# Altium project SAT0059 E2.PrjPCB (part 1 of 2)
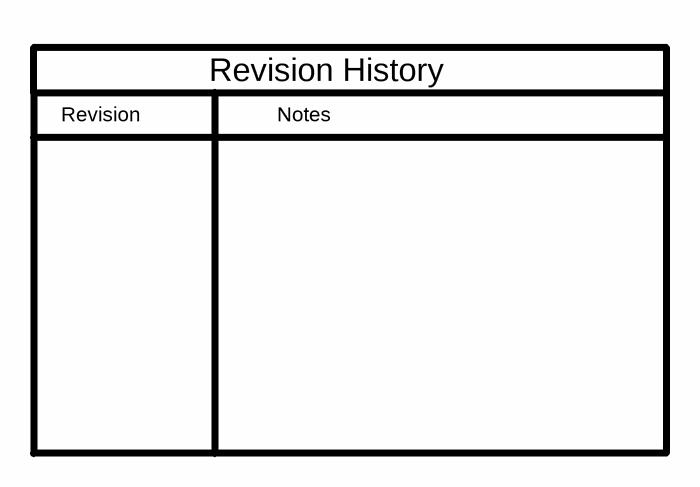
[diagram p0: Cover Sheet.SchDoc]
TechSupport: http://www.ti.com/support; SCH_Rev: E2; PRJ_Title: Touchscreen LCD (TIDA-00169); PRJ_Number: SAT0059; PRJ_Engineer: B. Shaffer; PRJ_Customer: Public Release; PCB_Rev: E2; PCB_Layout: Krypton Solutions; CopyrightYear: 2014
8 sheets, 276 parts. Net scope: global (net labels, ports and power ports of the same name join across sheets).
Board file: SAT0059 E2.PcbDoc
Sheets:
  Cover Sheet.SchDoc
  Power Supplies.SchDoc
  Deserializer.SchDoc
  LED Driver.SchDoc
  Haptic Drivers.SchDoc
  MCU.SchDoc
  Connectors.SchDoc
  Hardware.SchDoc

## Sheet Cover Sheet.SchDoc: Cover Sheet
size 431 x 279 mm; Date: Not shown in title block; ApprovedBy: Not shown in title block; CheckedBy: Not shown in title block; Author: Not shown in title block; CompanyName: Not shown in title block; DrawnBy: B. Shaffer; Engineer: Not shown in title block; Organization: Not shown in title block; Address1: Not shown in title block; Address2: Not shown in title block; Address3: Not shown in title block; Address4: Not shown in title block; DocumentNumber: 1; Revision: Use project parameter SCH_Rev; SheetNumber: 1; SheetTotal: 8; PageSetup: Record=PageOptions|CenterHorizontal=True|CenterVertical=True|PrintScale=1.00|XCorrection=1.00|YCorrection=1.00|PrintKind=0|BorderSize=5000000|LeftOffset=0|BottomOffset=0|Orientation=2|PaperLength=1000|PaperWidth=1000|Scale=100|PaperSource=15|PrintQuality=600|MediaType=1|DitherType=10|PaperKind=Letter|PrintScaleMode=1

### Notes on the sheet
- Revision
- Notes
- Revision History

## Sheet Power Supplies.SchDoc: Power Supply
size 431 x 279 mm; Date: Not shown in title block; ApprovedBy: Not shown in title block; CheckedBy: Not shown in title block; Author: Not shown in title block; CompanyName: Not shown in title block; DrawnBy: B. Shaffer; Engineer: Not shown in title block; Organization: Not shown in title block; Address1: Not shown in title block; Address2: Not shown in title block; Address3: Not shown in title block; Address4: Not shown in title block; DocumentNumber: 2; Revision: Use project parameter SCH_Rev; SheetNumber: 2; SheetTotal: 8; PageSetup: Record=PageOptions|CenterHorizontal=True|CenterVertical=True|PrintScale=0.96|XCorrection=1.00|YCorrection=1.00|PrintKind=0|BorderSize=5000000|LeftOffset=0|BottomOffset=0|Orientation=2|PaperLength=1000|PaperWidth=1000|Scale=100|PaperSource=15|PrintQuality=600|MediaType=1|DitherType=10|PaperKind=11x17|PrintScaleMode=1
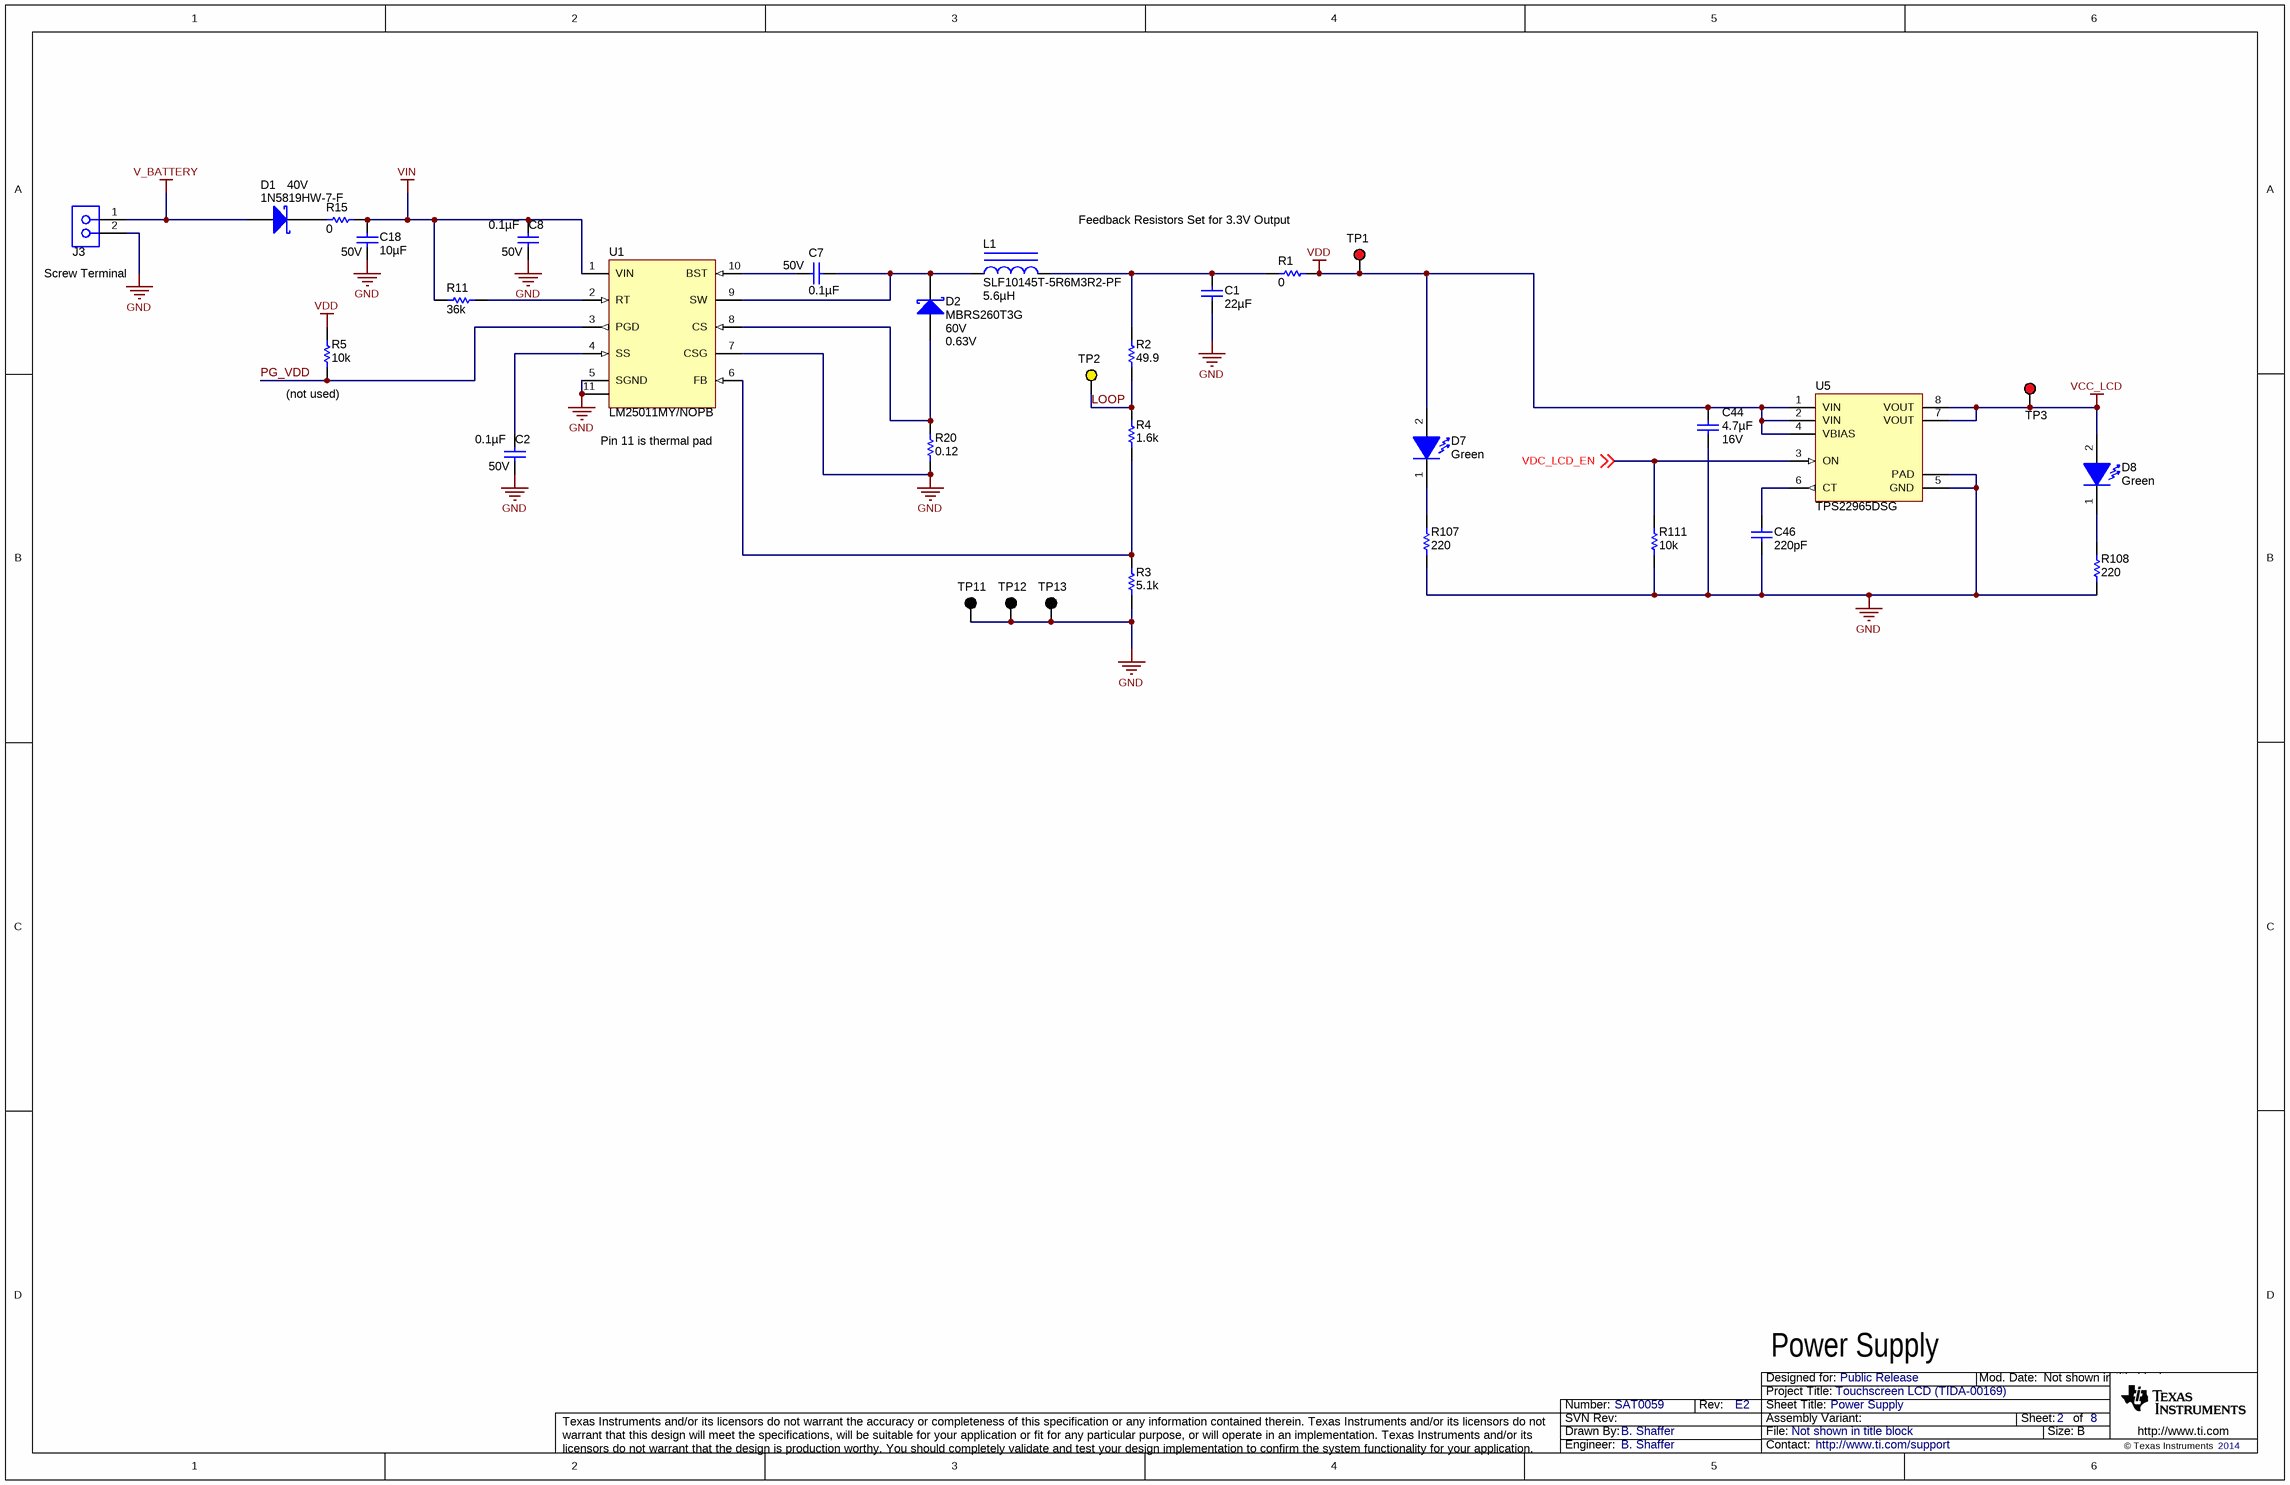
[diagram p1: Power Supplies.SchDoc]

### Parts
C1  ValueDisplayed: 22µF  [1210]  (hidden comment: C3225X7R1C226M)
C2  ValueDisplayed: 0.1µF  Value2: 50V  [0603]  (hidden comment: C1608X7R1H104K)
C7  ValueDisplayed: 0.1µF  Value2: 50V  [0603]  (hidden comment: C1608X7R1H104K)
C8  ValueDisplayed: 0.1µF  Value2: 50V  [0603]  (hidden comment: C1608X7R1H104K)
C18  ValueDisplayed: 10µF  Value2: 50V  [2220]  (hidden comment: C5750X7R1H106M)
C44  ValueDisplayed: 4.7µF  Value2: 16V  [0805_HV]  (hidden comment: EMK212BJ475KG-T)
C46  ValueDisplayed: 220pF  [0603]  (hidden comment: 06035A221JAT2A)
D1  1N5819HW-7-F  value 40V  [SOD-123]
D2  MBRS260T3G  value 60V  Value2: 0.63V  [SMB]
D7  value Green  [SML-P1_GREEN]  (hidden comment: SML-P12PTT86)
D8  value Green  [SML-P1_GREEN]  (hidden comment: SML-P12PTT86)
J3  1727010  [PhoenixConact_1727010]  (value not drawn)
L1  SLF10145T-5R6M3R2-PF  ValueDisplayed: 5.6µH  [SLF10145]
R1  value 0  [1210M]  (hidden comment: MCR25JZHJ000)
R2  value 49.9  [0402]  (hidden comment: CRCW040249R9FKED)
R3  value 5.1k  [0603]  (hidden comment: RC0603JR-075K1L)
R4  value 1.6k  [0603]  (hidden comment: RC0603JR-071K6L)
R5  value 10k  [0603]  (hidden comment: CRCW060310K0JNEA)
R11  value 36k  [0603]  (hidden comment: CRCW060336K0JNEA)
R15  value 0  [0603]  (hidden comment: CRCW06030000Z0EA)
R20  value 0.12  [1210M]  (hidden comment: ERJ14RSJR12U)
R107  value 220  [0402]  (hidden comment: CRCW0402220RJNED)
R108  value 220  [0402]  (hidden comment: CRCW0402220RJNED)
R111  value 10k  [0603]  (hidden comment: CRCW060310K0JNEA)
TP1  5000  [Keystone5000]  (value not drawn)
TP2  5004  [Keystone5004]  (value not drawn)
TP3  5000  [Keystone5000]  (value not drawn)
TP11  5001  [Keystone5001]  (value not drawn)
TP12  5001  [Keystone5001]  (value not drawn)
TP13  5001  [Keystone5001]  (value not drawn)
U1  LM25011MY/NOPB  [DGQ0010A_N]
U5  TPS22965DSG  [DSG0008A]

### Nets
GND: C1.2 C2.2 C8.2 C18.2 C44.2 C46.2 J3.2 R3.1 R20.1 R107.1 R108.1 R111.2 TP11.1 TP12.1 TP13.1 U1.5(SGND) U1.7(CSG) U1.11(PAD) U5.5(GND) U5.9(PAD)
V_BATTERY: D1.2(A) J3.1
VCC_LCD: D8.2(A) TP3.1 U5.7(VOUT) U5.8(VOUT)
VDD: C44.1 D7.2(A) R1.2 R5.1 TP1.1 U5.1(VIN) U5.2(VIN) U5.4(VBIAS)
VIN: C8.1 C18.1 R11.1 R15.1 U1.1(VIN)
LOOP: R2.1 R4.2 TP2.1
PG_VDD: R5.2 U1.3(PGD)
VDC_LCD_EN: R111.1 U5.3(ON) ; off-sheet VDC_LCD_EN
NetC1_1: C1.1 L1.2 R1.1 R2.2
NetC2_1: C2.1 U1.4(SS)
NetC7_1: C7.1 D2.1(K) L1.1 U1.9(SW)
NetC7_2: C7.2 U1.10(BST)
NetC46_1: C46.1 U5.6(CT)
NetD1_1: D1.1(K) R15.2
NetD2_2: D2.2(A) R20.2 U1.8(CS)
NetD7_1: D7.1(K) R107.2
NetD8_1: D8.1(K) R108.2
NetR3_2: R3.2 R4.1 U1.6(FB)
NetR11_2: R11.2 U1.2(RT)

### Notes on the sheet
- Feedback Resistors Set for 3.3V Output
- (near J3) Screw Terminal
- (near R5) (not used)
- (near U1) Pin 11 is thermal pad
- Power Supply

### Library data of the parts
C1 = C3225X7R1C226M: CAP, CERM, 22uF, 16V, +/-20%, X7R, 1210; Manufacturer: TDK; Polarized: N; CompType: Capacitor; U/M: EA; Cap_F: 0.000022; Tolerance_%: 20; ESR_Ohm: 0.002; Value1: 0.002 ohm; VDC_V: 16; IRMS_A: 8.11; TaMin_C: -55; TaMax_C: 125
C2 C7 C8 = C1608X7R1H104K: CAP, CERM, 0.1uF, 50V, +/-10%, X7R, 0603; Manufacturer: TDK; Polarized: N; CompType: Capacitor; U/M: EA; Cap_F: 0.0000001; Tolerance_%: 10; ESR_Ohm: 0.017; Value1: 0.017 ohm; VDC_V: 50; TaMin_C: -55; TaMax_C: 125
C18 = C5750X7R1H106M: CAP, CERM, 10uF, 50V, +/-20%, X7R, 2220; Manufacturer: TDK; Polarized: N; CompType: Capacitor; U/M: EA; Cap_F: 0.00001; Tolerance_%: 20; ESR_Ohm: 0.003; Value1: 0.003 ohm; VDC_V: 50; IRMS_A: 5.5; TaMin_C: -55; TaMax_C: 125
C44 = EMK212BJ475KG-T: CAP, CERM, 4.7uF, 16V, +/-10%, X5R, 0805; Manufacturer: Taiyo Yuden; Polarized: N; CompType: Capacitor; U/M: EA; Cap_F: 0.0000047; Tolerance_%: 10; Value1: Unknown; VDC_V: 16; TaMin_C: -55; TaMax_C: 85; Cap_Case: 0805
C46 = 06035A221JAT2A: CAP, CERM, 220pF, 50V, +/-5%, C0G/NP0, 0603; Manufacturer: AVX; Polarized: N; CompType: Capacitor; U/M: EA; Cap_F: 0.00000000022; Tolerance_%: 5; ESR_Ohm: 0.083; Value1: 0.083 ohm; VDC_V: 50; TaMin_C: -55; TaMax_C: 125
D1 = 1N5819HW-7-F: Diode, Schottky, 40V, 1A, SOD-123; Manufacturer: Diodes Inc.; U/M: EA; Vf_V: 0.45; Value2: 0.45V; Io_A: 1; Vr_V: 40; TJmax_C: 125
D2 = MBRS260T3G: Diode, Schottky, 60V, 2A, SMB; Manufacturer: ON Semiconductor; U/M: EA; Vf_V: 0.63; Io_A: 2; Vr_V: 60; TJmax_C: 125; RJC_CperW: 24
D7 D8 = SML-P12PTT86: LED, Green, SMD; Manufacturer: Rohm; Type: AlInGaP; Vf_V: 2.2; Value2: 2.2V; Io_A: 0.02; Value1: W; U/M: EA
J3 = 1727010: Conn Term Block, 2POS, 3.81mm PCB; Manufacturer: Phoenix Contact; Alternate Manufacturer: Any; Alternate PartNumber: Equivalent; Value: 2x1; CompType: Terminal Block; U/M: EA
L1 = SLF10145T-5R6M3R2-PF: Inductor, Shielded, Ferrite, 5.6uH, 3.8A, 0.0264 ohm, SMD; Manufacturer: TDK; Ind_H: 5.6E-6; Imax_A: 3.8; Irms: 3.2A @ 30C rise; Isat: 3.8A @ 10% inductance drop; DCR_ohm: 0.0264; U/M: EA
R1 = MCR25JZHJ000: RES, 0 ohm, 5%, 0.25W, 1210; Manufacturer: Rohm; CompType: Resistor; Value_Code: 0000; Tolerance_%: 5; Power_W: 0.25; VDC_V: 200; TempCo: 20 ppm/C; EIA_Code: E24; U/M: EA
R2 = CRCW040249R9FKED: RES, 49.9 ohm, 1%, 0.063W, 0402; Manufacturer: Vishay-Dale; CompType: Resistor; Value_Code: 49R9; Tolerance_%: 1; Power_W: 0.063; VDC_V: 50; TempCo: 100 ppm/C; EIA_Code: E96; U/M: EA
R3 = RC0603JR-075K1L: RES, 5.1k ohm, 5%, 0.1W, 0603; Manufacturer: Yageo America; CompType: Resistor; Res_ohm: 5100; Value_Code: 5k10; Tolerance_%: 5; Power_W: 0.1; VDC_V: 50; TempCo: 100 ppm/C; EIA_Code: E24; U/M: EA
R4 = RC0603JR-071K6L: RES, 1.6k ohm, 5%, 0.1W, 0603; Manufacturer: Yageo America; CompType: Resistor; Res_ohm: 1600; Value_Code: 1k60; Tolerance_%: 5; Power_W: 0.1; VDC_V: 50; TempCo: 100 ppm/C; EIA_Code: E24; U/M: EA
R5 R111 = CRCW060310K0JNEA: RES, 10k ohm, 5%, 0.1W, 0603; Manufacturer: Vishay-Dale; CompType: Resistor; Res_ohm: 10000; Value_Code: 10k0; Tolerance_%: 5; Power_W: 0.1; VDC_V: 75; TempCo: 200 ppm/C; EIA_Code: E24; U/M: EA
R11 = CRCW060336K0JNEA: RES, 36k ohm, 5%, 0.1W, 0603; Manufacturer: Vishay-Dale; CompType: Resistor; Res_ohm: 36000; Value_Code: 36k0; Tolerance_%: 5; Power_W: 0.1; VDC_V: 75; TempCo: 200 ppm/C; EIA_Code: E24; U/M: EA
R15 = CRCW06030000Z0EA: RES, 0 ohm, 5%, 0.1W, 0603; Manufacturer: Vishay-Dale; CompType: Resistor; Value_Code: 0000; Tolerance_%: 5; Power_W: 0.1; VDC_V: 75; TempCo: 200 ppm/C; EIA_Code: E24; U/M: EA
R20 = ERJ14RSJR12U: RES, 0.12 ohm, 5%, 0.25W, 1210; Manufacturer: Panasonic; CompType: Resistor; Value_Code: R120; Tolerance_%: 5; Power_W: 0.25; TempCo: 200 ppm/C; EIA_Code: E24; U/M: EA
R107 R108 = CRCW0402220RJNED: RES, 220 ohm, 5%, 0.063W, 0402; Manufacturer: Vishay-Dale; Alternate Manufacturer: Any; Alternate PartNumber: Equivalent; CompType: Resistor; Value_Code: 220R; Tolerance_%: 5; Power_W: 0.063; VDC_V: 50; TempCo: 200 ppm/C; EIA_Code: E24; U/M: EA
TP1 TP3 = 5000: Test Point, Miniature, Red, TH; Manufacturer: Keystone; CompType: Test Point Loop; U/M: EA
TP2 = 5004: Test Point, Miniature, Yellow, TH; Manufacturer: Keystone; CompType: Test Point Loop; U/M: EA
TP11-TP13 = 5001: Test Point, Miniature, Black, TH; Manufacturer: Keystone; CompType: Test Point Loop; U/M: EA
U1 = LM25011MY/NOPB: 42V 2A Constant On-Time Switching Regulator With Adjustable Current Limit, DGQ0010A; Alternate Manufacturer: None; Manufacturer: Texas Instruments; SymbolCreator: a0411947; CompType: IC; U/M: EA
U5 = TPS22965DSG: Single Channel, Ultra-Low Resistance Load Switch, DSG0008A; Alternate Manufacturer: None; Manufacturer: Texas Instruments; SymbolCreator: a0411947; CompType: IC; U/M: EA

## Sheet Deserializer.SchDoc: Deserializer
size 431 x 279 mm; Date: Not shown in title block; ApprovedBy: Not shown in title block; CheckedBy: Not shown in title block; Author: Not shown in title block; CompanyName: Not shown in title block; DrawnBy: B. Shaffer; Engineer: Not shown in title block; Organization: Not shown in title block; Address1: Not shown in title block; Address2: Not shown in title block; Address3: Not shown in title block; Address4: Not shown in title block; DocumentNumber: 3; Revision: Use project parameter SCH_Rev; SheetNumber: 3; SheetTotal: 8; PageSetup: Record=PageOptions|CenterHorizontal=True|CenterVertical=True|PrintScale=0.96|XCorrection=1.00|YCorrection=1.00|PrintKind=0|BorderSize=5000000|LeftOffset=0|BottomOffset=0|Orientation=2|PaperLength=1000|PaperWidth=1000|Scale=100|PaperSource=15|PrintQuality=600|MediaType=1|DitherType=10|PaperKind=11x17|PrintScaleMode=1
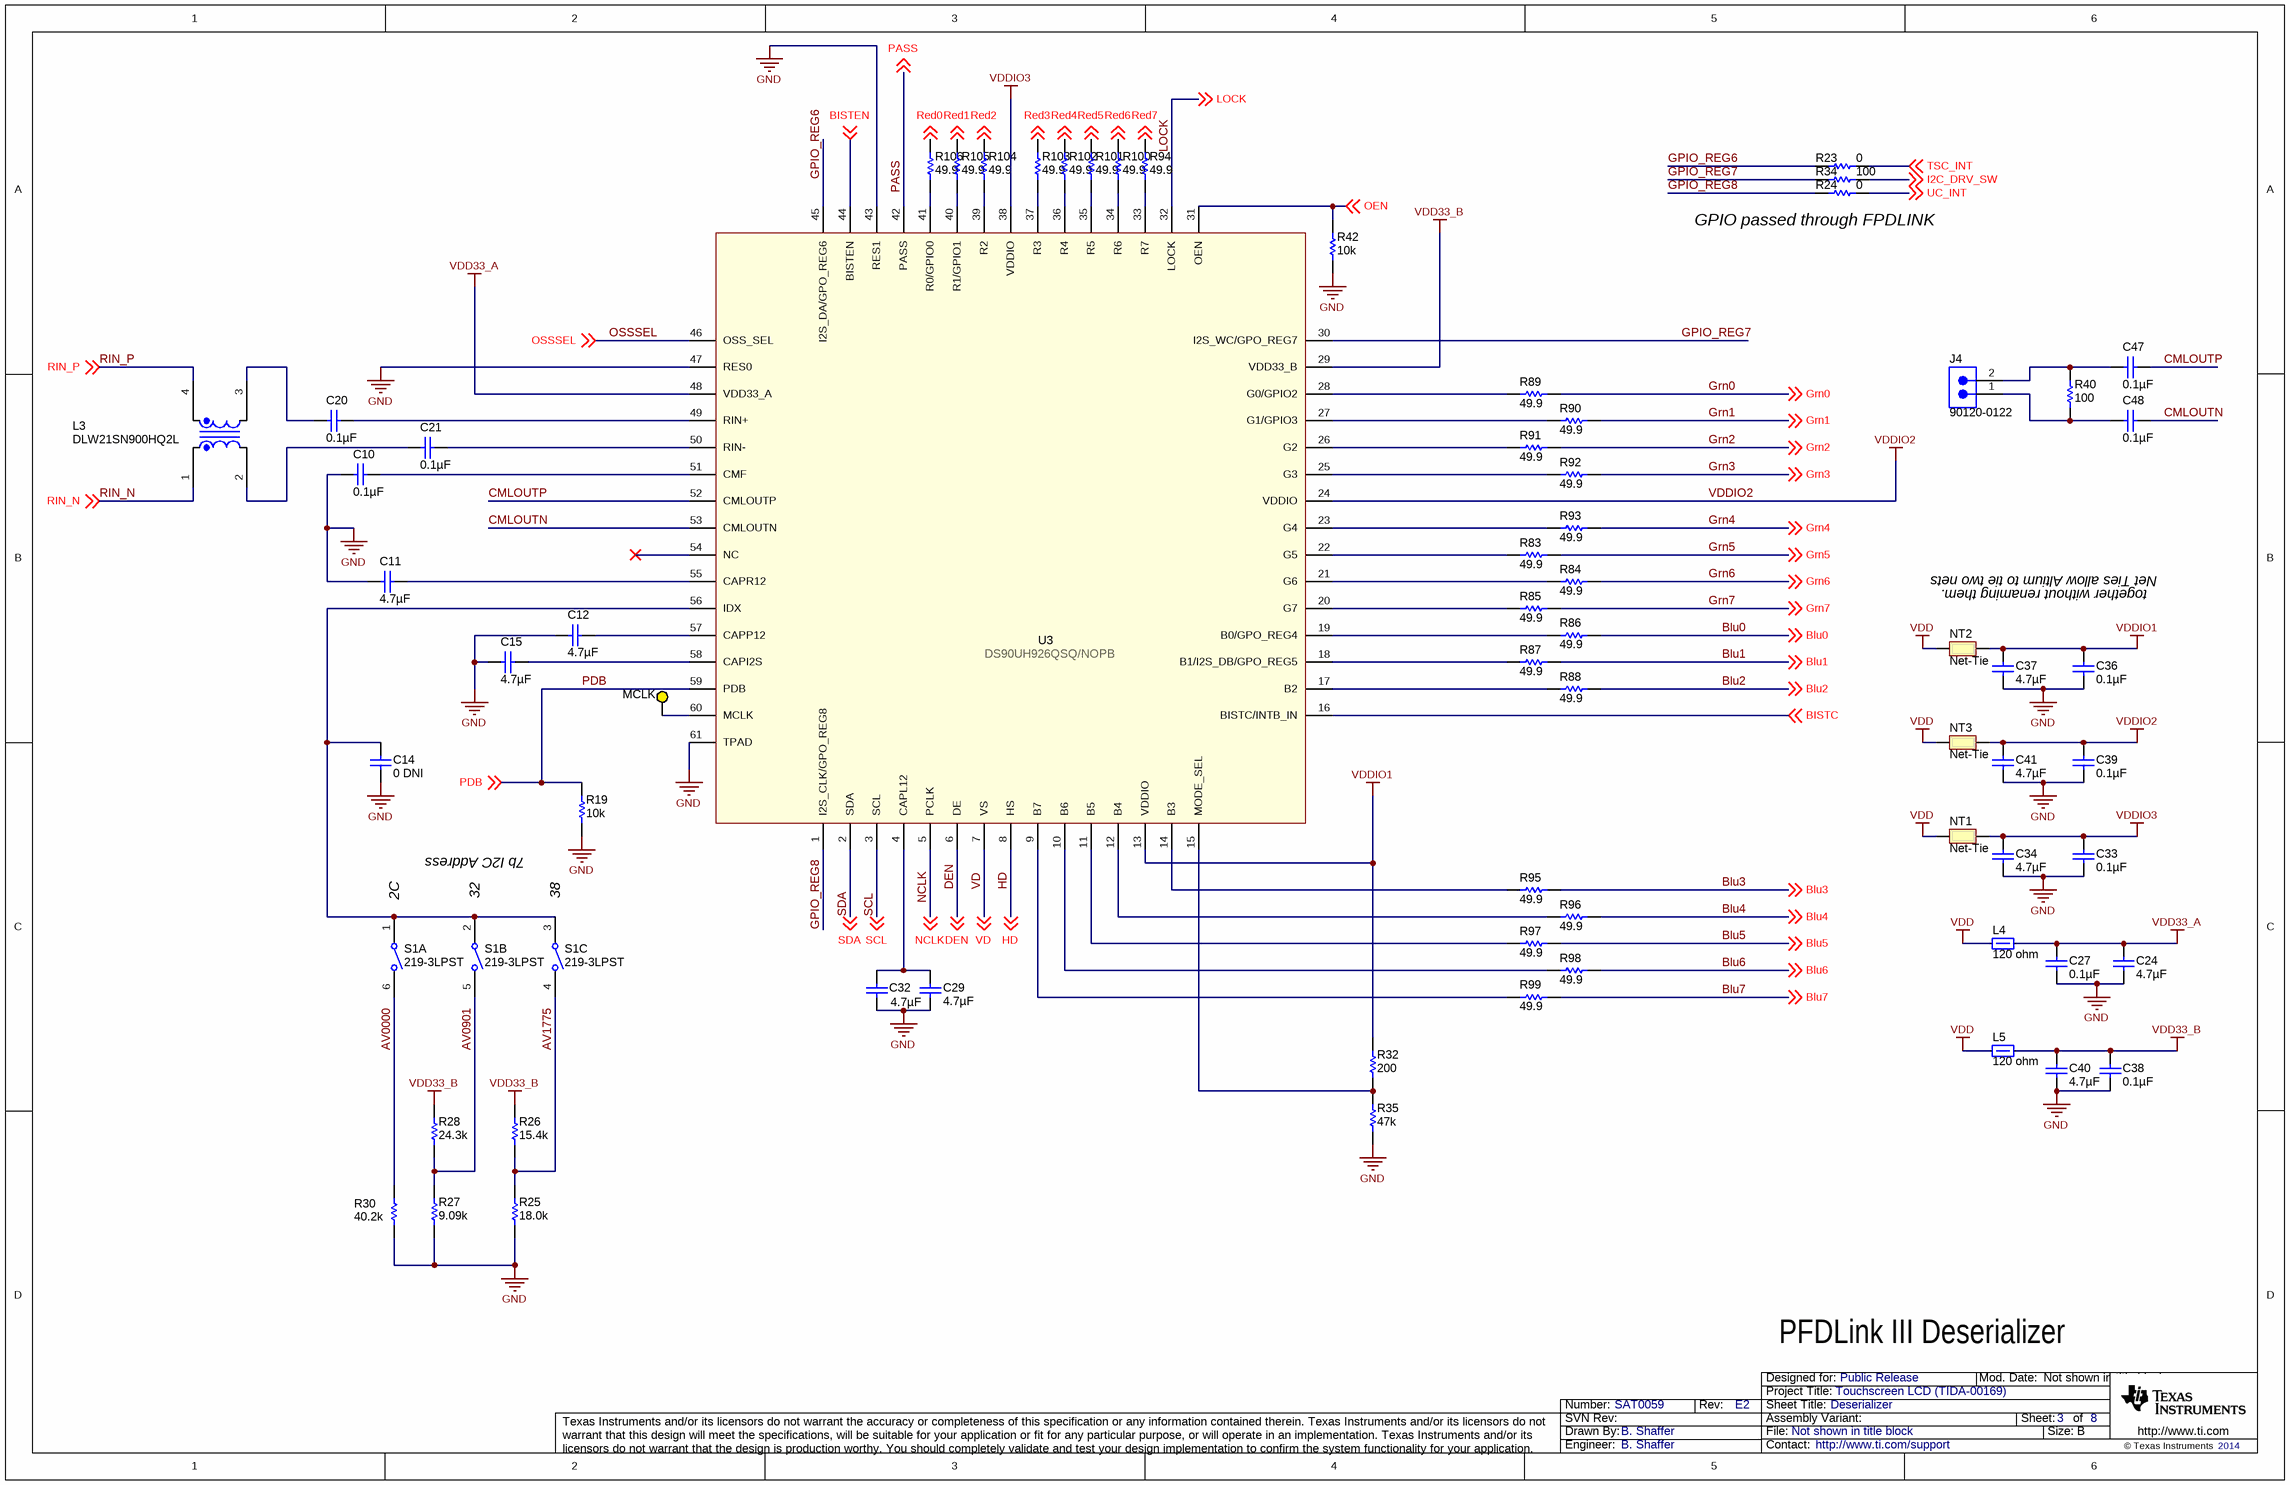
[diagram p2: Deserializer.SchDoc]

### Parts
C10  ValueDisplayed: 0.1µF  [0603]  (hidden comment: GCM188R71H104KA57B)
C11  ValueDisplayed: 4.7µF  [0805_HV]  (hidden comment: EMK212BJ475KG-T)
C12  ValueDisplayed: 4.7µF  [0805_HV]  (hidden comment: GRM21BR71A475KA73L)
C14  ValueDisplayed: 0 DNI  [0805]  (hidden comment: GCM188R71H104KA57B)
C15  ValueDisplayed: 4.7µF  [0805_HV]  (hidden comment: GRM21BR71A475KA73L)
C20  ValueDisplayed: 0.1µF  [0603]  (hidden comment: GCM188R71H104KA57B)
C21  ValueDisplayed: 0.1µF  [0603]  (hidden comment: GCM188R71H104KA57B)
C24  ValueDisplayed: 4.7µF  [0805_HV]  (hidden comment: GRM21BR71A475KA73L)
C27  ValueDisplayed: 0.1µF  [0603]  (hidden comment: 0603YC104JAT2A)
C29  ValueDisplayed: 4.7µF  [0805_HV]  (hidden comment: GRM21BR71A475KA73L)
C32  ValueDisplayed: 4.7µF  [0805_HV]  (hidden comment: GRM21BR71A475KA73L)
C33  ValueDisplayed: 0.1µF  [0603]  (hidden comment: 0603YC104JAT2A)
C34  ValueDisplayed: 4.7µF  [0805_HV]  (hidden comment: GRM21BR71A475KA73L)
C36  ValueDisplayed: 0.1µF  [0603]  (hidden comment: 0603YC104JAT2A)
C37  ValueDisplayed: 4.7µF  [0805_HV]  (hidden comment: GRM21BR71A475KA73L)
C38  ValueDisplayed: 0.1µF  [0603]  (hidden comment: 0603YC104JAT2A)
C39  ValueDisplayed: 0.1µF  [0603]  (hidden comment: 0603YC104JAT2A)
C40  ValueDisplayed: 4.7µF  [0805_HV]  (hidden comment: GRM21BR71A475KA73L)
C41  ValueDisplayed: 4.7µF  [0805_HV]  (hidden comment: GRM21BR71A475KA73L)
C47  ValueDisplayed: 0.1µF  [0603]  (hidden comment: GCM188R71H104KA57B)
C48  ValueDisplayed: 0.1µF  [0603]  (hidden comment: GCM188R71H104KA57B)
J4  90120-0122  [CONN_90120-0122]
L3  DLW21SN900HQ2L  [IND_DLW21S]
L4  value 120 ohm  [0603]  (hidden comment: BLM18SG121TN1D)
L5  value 120 ohm  [0603]  (hidden comment: BLM18SG121TN1D)
MCLK  5004  [Keystone5004]  (value not drawn)
NT1  Net-Tie  [Net-Tie_10mil]  (net tie, no BOM)
NT2  Net-Tie  [Net-Tie_10mil]  (net tie, no BOM)
NT3  Net-Tie  [Net-Tie_10mil]  (net tie, no BOM)
R19  value 10k  [0402]  (hidden comment: CRCW040210K0JNED)
R23  value 0  [0603]  (hidden comment: CRCW06030000Z0EA)
R24  value 0  [0603]  (hidden comment: CRCW06030000Z0EA)
R25  value 18.0k  [0603]  (hidden comment: RC0603FR-0718KL)
R26  value 15.4k  [0603]  (hidden comment: CRCW060315K4FKEA)
R27  value 9.09k  [0603]  (hidden comment: CRCW06039K09FKEA)
R28  value 24.3k  [0603]  (hidden comment: CRCW060324K3FKEA)
R30  value 40.2k  [0805_HV]  (hidden comment: CRCW080540K2FKEA)
R32  value 200  [0603]  (hidden comment: CRCW0603200RFKEA)
R34  value 100  [0603]  (hidden comment: CRCW0603100RFKEA)
R35  value 47k  [0603]  (hidden comment: CRCW060347K0JNEA)
R40  value 100  [0603]  (hidden comment: CRCW0603100RFKEA)
R42  value 10k  [0402]  (hidden comment: CRCW040210K0JNED)
R83  value 49.9  [0402]  (hidden comment: CRCW040249R9FKED)
R84  value 49.9  [0402]  (hidden comment: CRCW040249R9FKED)
R85  value 49.9  [0402]  (hidden comment: CRCW040249R9FKED)
R86  value 49.9  [0402]  (hidden comment: CRCW040249R9FKED)
R87  value 49.9  [0402]  (hidden comment: CRCW040249R9FKED)
R88  value 49.9  [0402]  (hidden comment: CRCW040249R9FKED)
R89  value 49.9  [0402]  (hidden comment: CRCW040249R9FKED)
R90  value 49.9  [0402]  (hidden comment: CRCW040249R9FKED)
R91  value 49.9  [0402]  (hidden comment: CRCW040249R9FKED)
R92  value 49.9  [0402]  (hidden comment: CRCW040249R9FKED)
R93  value 49.9  [0402]  (hidden comment: CRCW040249R9FKED)
R94  value 49.9  [0402]  (hidden comment: CRCW040249R9FKED)
R95  value 49.9  [0402]  (hidden comment: CRCW040249R9FKED)
R96  value 49.9  [0402]  (hidden comment: CRCW040249R9FKED)
R97  value 49.9  [0402]  (hidden comment: CRCW040249R9FKED)
R98  value 49.9  [0402]  (hidden comment: CRCW040249R9FKED)
R99  value 49.9  [0402]  (hidden comment: CRCW040249R9FKED)
R100  value 49.9  [0402]  (hidden comment: CRCW040249R9FKED)
R101  value 49.9  [0402]  (hidden comment: CRCW040249R9FKED)
R102  value 49.9  [0402]  (hidden comment: CRCW040249R9FKED)
R103  value 49.9  [0402]  (hidden comment: CRCW040249R9FKED)
R104  value 49.9  [0402]  (hidden comment: CRCW040249R9FKED)
R105  value 49.9  [0402]  (hidden comment: CRCW040249R9FKED)
R106  value 49.9  [0402]  (hidden comment: CRCW040249R9FKED)
S1  219-3LPST  [SW_219-3LPST]  (parts A,B,C of 3)
U3  DS90UH926QSQ/NOPB  [DS90UH926QSQ/NOPB]

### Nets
GND: C10.2 C11.2 C12.2 C14.2 C15.2 C24.2 C27.2 C29.2 C32.2 C33.2 C34.2 C36.2 C37.2 C38.2 C39.2 C40.2 C41.2 R19.1 R25.1 R27.1 R30.1 R35.1 R42.1 U3.43(RES1) U3.47(RES0) U3.61(TPAD)
VDD: L4.2 L5.2 NT1.1 NT2.1 NT3.1
VDD33_A: C24.1 C27.1 L4.1 U3.48(VDD33_A)
VDD33_B: C38.1 C40.1 L5.1 R26.2 R28.2 U3.29(VDD33_B)
VDDIO1: C36.1 C37.1 NT2.2 R32.2 U3.13(VDDIO)
VDDIO2: C39.1 C41.1 NT3.2 U3.24(VDDIO)
VDDIO3: C33.1 C34.1 NT1.2 U3.38(VDDIO)
AV0000: R30.2 S1.6(B1)
AV0901: R27.2 R28.1 S1.5(B2)
AV1775: R25.2 R26.1 S1.4(B3)
BISTC: U3.16(BISTC/INTB_IN) ; off-sheet BISTC
BISTEN: U3.44(BISTEN) ; off-sheet BISTEN
Blu0: R86.2 ; off-sheet Blu0
Blu1: R87.2 ; off-sheet Blu1
Blu2: R88.2 ; off-sheet Blu2
Blu3: R95.2 ; off-sheet Blu3
Blu4: R96.2 ; off-sheet Blu4
Blu5: R97.2 ; off-sheet Blu5
Blu6: R98.2 ; off-sheet Blu6
Blu7: R99.2 ; off-sheet Blu7
CMLOUTN: C48.1 U3.53(CMLOUTN)
CMLOUTP: C47.1 U3.52(CMLOUTP)
DEN: U3.6(DE) ; off-sheet DEN
GPIO_REG6: R23.2 U3.45(I2S_DA/GPO_REG6)
GPIO_REG7: R34.2 U3.30(I2S_WC/GPO_REG7)
GPIO_REG8: R24.2 U3.1(I2S_CLK/GPO_REG8)
Grn0: R89.2 ; off-sheet Grn0
Grn1: R90.2 ; off-sheet Grn1
Grn2: R91.2 ; off-sheet Grn2
Grn3: R92.2 ; off-sheet Grn3
Grn4: R93.2 ; off-sheet Grn4
Grn5: R83.2 ; off-sheet Grn5
Grn6: R84.2 ; off-sheet Grn6
Grn7: R85.2 ; off-sheet Grn7
HD: U3.8(HS) ; off-sheet HD
I2C_DRV_SW: R34.1 ; off-sheet I2C_DRV_SW
LOCK: U3.32(LOCK) ; off-sheet LOCK
NCLK: U3.5(PCLK) ; off-sheet NCLK
OEN: R42.2 U3.31(OEN) ; off-sheet OEN
OSSSEL: U3.46(OSS_SEL) ; off-sheet OSSSEL
PASS: U3.42(PASS) ; off-sheet PASS
PDB: R19.2 U3.59(PDB) ; off-sheet PDB
Red0: R106.2 ; off-sheet Red0
Red1: R105.2 ; off-sheet Red1
Red2: R104.2 ; off-sheet Red2
Red3: R103.2 ; off-sheet Red3
Red4: R102.2 ; off-sheet Red4
Red5: R101.2 ; off-sheet Red5
Red6: R100.2 ; off-sheet Red6
Red7: R94.2 ; off-sheet Red7
RIN_N: L3.1 ; off-sheet RIN_N
RIN_P: L3.4 ; off-sheet RIN_P
SCL: U3.3(SCL) ; off-sheet SCL
SDA: U3.2(SDA) ; off-sheet SDA
TSC_INT: R23.1 ; off-sheet TSC_INT
UC_INT: R24.1 ; off-sheet UC_INT
VD: U3.7(VS) ; off-sheet VD
NetC10_1: C10.1 U3.51(CMF)
NetC11_1: C11.1 U3.55(CAPR12)
NetC12_1: C12.1 U3.57(CAPP12)
NetC14_1: C14.1 S1.1(A1) S1.2(A2) S1.3(A3) U3.56(IDX)
NetC15_1: C15.1 U3.58(CAPI2S)
NetC20_1: C20.1 U3.49(RIN+)
NetC20_2: C20.2 L3.3
NetC21_1: C21.1 U3.50(RIN-)
NetC21_2: C21.2 L3.2
NetC29_1: C29.1 C32.1 U3.4(CAPL12)
NetC47_2: C47.2 J4.2 R40.2
NetC48_2: C48.2 J4.1 R40.1
NetMCLK_1: MCLK.1 U3.60(MCLK)
NetR32_1: R32.1 R35.2 U3.15(MODE_SEL)
NetR83_1: R83.1 U3.22(G5)
NetR84_1: R84.1 U3.21(G6)
NetR85_1: R85.1 U3.20(G7)
NetR86_1: R86.1 U3.19(B0/GPO_REG4)
NetR87_1: R87.1 U3.18(B1/I2S_DB/GPO_REG5)
NetR88_1: R88.1 U3.17(B2)
NetR89_1: R89.1 U3.28(G0/GPIO2)
NetR90_1: R90.1 U3.27(G1/GPIO3)
NetR91_1: R91.1 U3.26(G2)
NetR92_1: R92.1 U3.25(G3)
NetR93_1: R93.1 U3.23(G4)
NetR94_1: R94.1 U3.33(R7)
NetR95_1: R95.1 U3.14(B3)
NetR96_1: R96.1 U3.12(B4)
NetR97_1: R97.1 U3.11(B5)
NetR98_1: R98.1 U3.10(B6)
NetR99_1: R99.1 U3.9(B7)
NetR100_1: R100.1 U3.34(R6)
NetR101_1: R101.1 U3.35(R5)
NetR102_1: R102.1 U3.36(R4)
NetR103_1: R103.1 U3.37(R3)
NetR104_1: R104.1 U3.39(R2)
NetR105_1: R105.1 U3.40(R1/GPIO1)
NetR106_1: R106.1 U3.41(R0/GPIO0)

Not connected (* = marked no-connect by the designer): U3 54(NC)*

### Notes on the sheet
- (near R24) GPIO passed through FPDLINK
- Net Ties allow Altium to tie two nets
- together without renaming them.
- (near S1) 2C
- (near S1) 32
- 7b I2C Address
- 38
- PFDLink III Deserializer

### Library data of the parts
C10 C20 C21 C47 C48 = GCM188R71H104KA57B: CAP, CERM, 0.1uF, 50V, +/-10%, X7R, 0603; Manufacturer: MuRata; Polarized: N; CompType: Capacitor; U/M: EA; Cap_F: 0.0000001; Tolerance_%: 10; ESR_Ohm: 0.02; Value1: 0.02 ohm; VDC_V: 50; IRMS_A: 1.84; TaMin_C: -55; TaMax_C: 125
C11 = EMK212BJ475KG-T: as C44 on sheet Power Supplies
C12 C15 C24 C29 C32 C34 C37 C40 C41 = GRM21BR71A475KA73L: CAP, CERM, 4.7uF, 10V, +/-10%, X7R, 0805; Manufacturer: MuRata; Polarized: N; CompType: Capacitor; U/M: EA; Cap_F: 0.0000047; Tolerance_%: 10; Value1: Unknown; TaMin_C: -55; TaMax_C: 125; Cap_Case: 0805
C14 = GCM188R71H104KA57B: CAP, CERM, 0.1uF, 50V, +/-10%, X7R, 0603; Manufacturer: MuRata; Polarized: N; CompType: Capacitor; U/M: EA; Cap_F: 0.0000001; Tolerance_%: 10; ESR_Ohm: 0.02; Value1: 0.02 ohm; VDC_V: 50; IRMS_A: 1.84; TaMin_C: -55; TaMax_C: 125; Cap_Case: 0603
C27 C33 C36 C38 C39 = 0603YC104JAT2A: CAP, CERM, 0.1uF, 16V, +/-5%, X7R, 0603; Manufacturer: AVX; Polarized: N; CompType: Capacitor; U/M: EA; Cap_F: 0.0000001; Tolerance_%: 5; ESR_Ohm: 0.039; Value1: 0.039 ohm; VDC_V: 16; TaMin_C: -55; TaMax_C: 125
J4 = 90120-0122: Header, 100mil, 2x1, Tin plated, TH; Manufacturer: Molex; SymbolCreator: a0412235; U/M: EA
L3 = DLW21SN900HQ2L: Coupled inductor, 0.28A, 0.41 ohm, +/-25%, SMD; Manufacturer: MuRata; SymbolCreator: a0412235; DCR_ohm: 0.41; Isat: 0.28; Tolerance_%: 25
L4 L5 = BLM18SG121TN1D: 3A Ferrite Bead, 120 ohm @ 100MHz, SMD; Manufacturer: MuRata; Imax_A: 3; DCR_ohm: 0.025; Value1: 0.025 ohm; ZTyp@100MHz_Ohm: 120; U/M: EA
MCLK = 5004: as TP2 on sheet Power Supplies
NT1-NT3 = Net-Tie: Single point connection between nets.; SymbolCreator: codlsc
R19 R42 = CRCW040210K0JNED: RES, 10k ohm, 5%, 0.063W, 0402; Manufacturer: Vishay-Dale; CompType: Resistor; Res_ohm: 10000; Value_Code: 10k0; Tolerance_%: 5; Power_W: 0.063; VDC_V: 50; TempCo: 200 ppm/C; EIA_Code: E24; U/M: EA
R23 R24 = CRCW06030000Z0EA: as R15 on sheet Power Supplies
R25 = RC0603FR-0718KL: RES, 18.0k ohm, 1%, 0.1W, 0603; Manufacturer: Yageo America; CompType: Resistor; Res_ohm: 18000; Value_Code: 18k0; Tolerance_%: 1; Power_W: 0.1; VDC_V: 150; TempCo: 200 ppm/C; U/M: EA
R26 = CRCW060315K4FKEA: RES, 15.4k ohm, 1%, 0.1W, 0603; Manufacturer: Vishay-Dale; CompType: Resistor; Res_ohm: 15400; Value_Code: 15k4; Tolerance_%: 1; Power_W: 0.1; VDC_V: 75; TempCo: 100 ppm/C; EIA_Code: E96; U/M: EA
R27 = CRCW06039K09FKEA: RES, 9.09k ohm, 1%, 0.1W, 0603; Manufacturer: Vishay-Dale; CompType: Resistor; Res_ohm: 9090; Value_Code: 9k09; Tolerance_%: 1; Power_W: 0.1; VDC_V: 75; TempCo: 100 ppm/C; EIA_Code: E96; U/M: EA
R28 = CRCW060324K3FKEA: RES, 24.3k ohm, 1%, 0.1W, 0603; Manufacturer: Vishay-Dale; CompType: Resistor; Res_ohm: 24300; Value_Code: 24k3; Tolerance_%: 1; Power_W: 0.1; VDC_V: 75; TempCo: 100 ppm/C; EIA_Code: E96; U/M: EA
R30 = CRCW080540K2FKEA: RES, 40.2k ohm, 1%, 0.125W, 0805; Manufacturer: Vishay-Dale; CompType: Resistor; Res_ohm: 40200; Value_Code: 40k2; Tolerance_%: 1; Power_W: 0.125; VDC_V: 150; TempCo: 100 ppm/C; EIA_Code: E96; U/M: EA
R32 = CRCW0603200RFKEA: RES, 200 ohm, 1%, 0.1W, 0603; Manufacturer: Vishay-Dale; CompType: Resistor; Value_Code: 200R; Tolerance_%: 1; Power_W: 0.1; VDC_V: 75; TempCo: 100 ppm/C; EIA_Code: E96; U/M: EA
R34 R40 = CRCW0603100RFKEA: RES, 100 ohm, 1%, 0.1W, 0603; Manufacturer: Vishay-Dale; CompType: Resistor; Value_Code: 100R; Tolerance_%: 1; Power_W: 0.1; VDC_V: 75; TempCo: 100 ppm/C; EIA_Code: E96; U/M: EA
R35 = CRCW060347K0JNEA: RES, 47k ohm, 5%, 0.1W, 0603; Manufacturer: Vishay-Dale; CompType: Resistor; Res_ohm: 47000; Value_Code: 47k0; Tolerance_%: 5; Power_W: 0.1; VDC_V: 75; TempCo: 200 ppm/C; EIA_Code: E24; U/M: EA
R83-R106 = CRCW040249R9FKED: as R2 on sheet Power Supplies
S1 = 219-3LPST: Switch, Slide, SPST 3 poles, SMT; Manufacturer: CTS Electrocomponents; SymbolCreator: a0799628; VDC_V: 20; SwitchFunction: Off-On; PositionCount: 3; CurrentRating_mA: 100
U3 = DS90UH926QSQ/NOPB: IC SERIAL/DESERIAL 24 BIT 60-LLP; Manufacturer: Texas Instruments; Function: Deserializer; Data Rate: 2.975Gbps; Input Type: FPD-Link III, LVDS; Output Type: LVCMOS; Number of Inputs: 24; Number of Outputs: 1; Voltage - Supply: 3 V ~ 3.6 V

## Sheet LED Driver.SchDoc: LED Driver
size 431 x 279 mm; Date: Not shown in title block; ApprovedBy: Not shown in title block; CheckedBy: Not shown in title block; Author: Not shown in title block; CompanyName: Not shown in title block; DrawnBy: B. Shaffer; Engineer: Not shown in title block; Organization: Not shown in title block; Address1: Not shown in title block; Address2: Not shown in title block; Address3: Not shown in title block; Address4: Not shown in title block; DocumentNumber: 4; Revision: Use project parameter SCH_Rev; SheetNumber: 4; SheetTotal: 8; PageSetup: Record=PageOptions|CenterHorizontal=True|CenterVertical=True|PrintScale=0.96|XCorrection=1.00|YCorrection=1.00|PrintKind=0|BorderSize=5000000|LeftOffset=0|BottomOffset=0|Orientation=2|PaperLength=1000|PaperWidth=1000|Scale=100|PaperSource=15|PrintQuality=600|MediaType=1|DitherType=10|PaperKind=11x17|PrintScaleMode=1
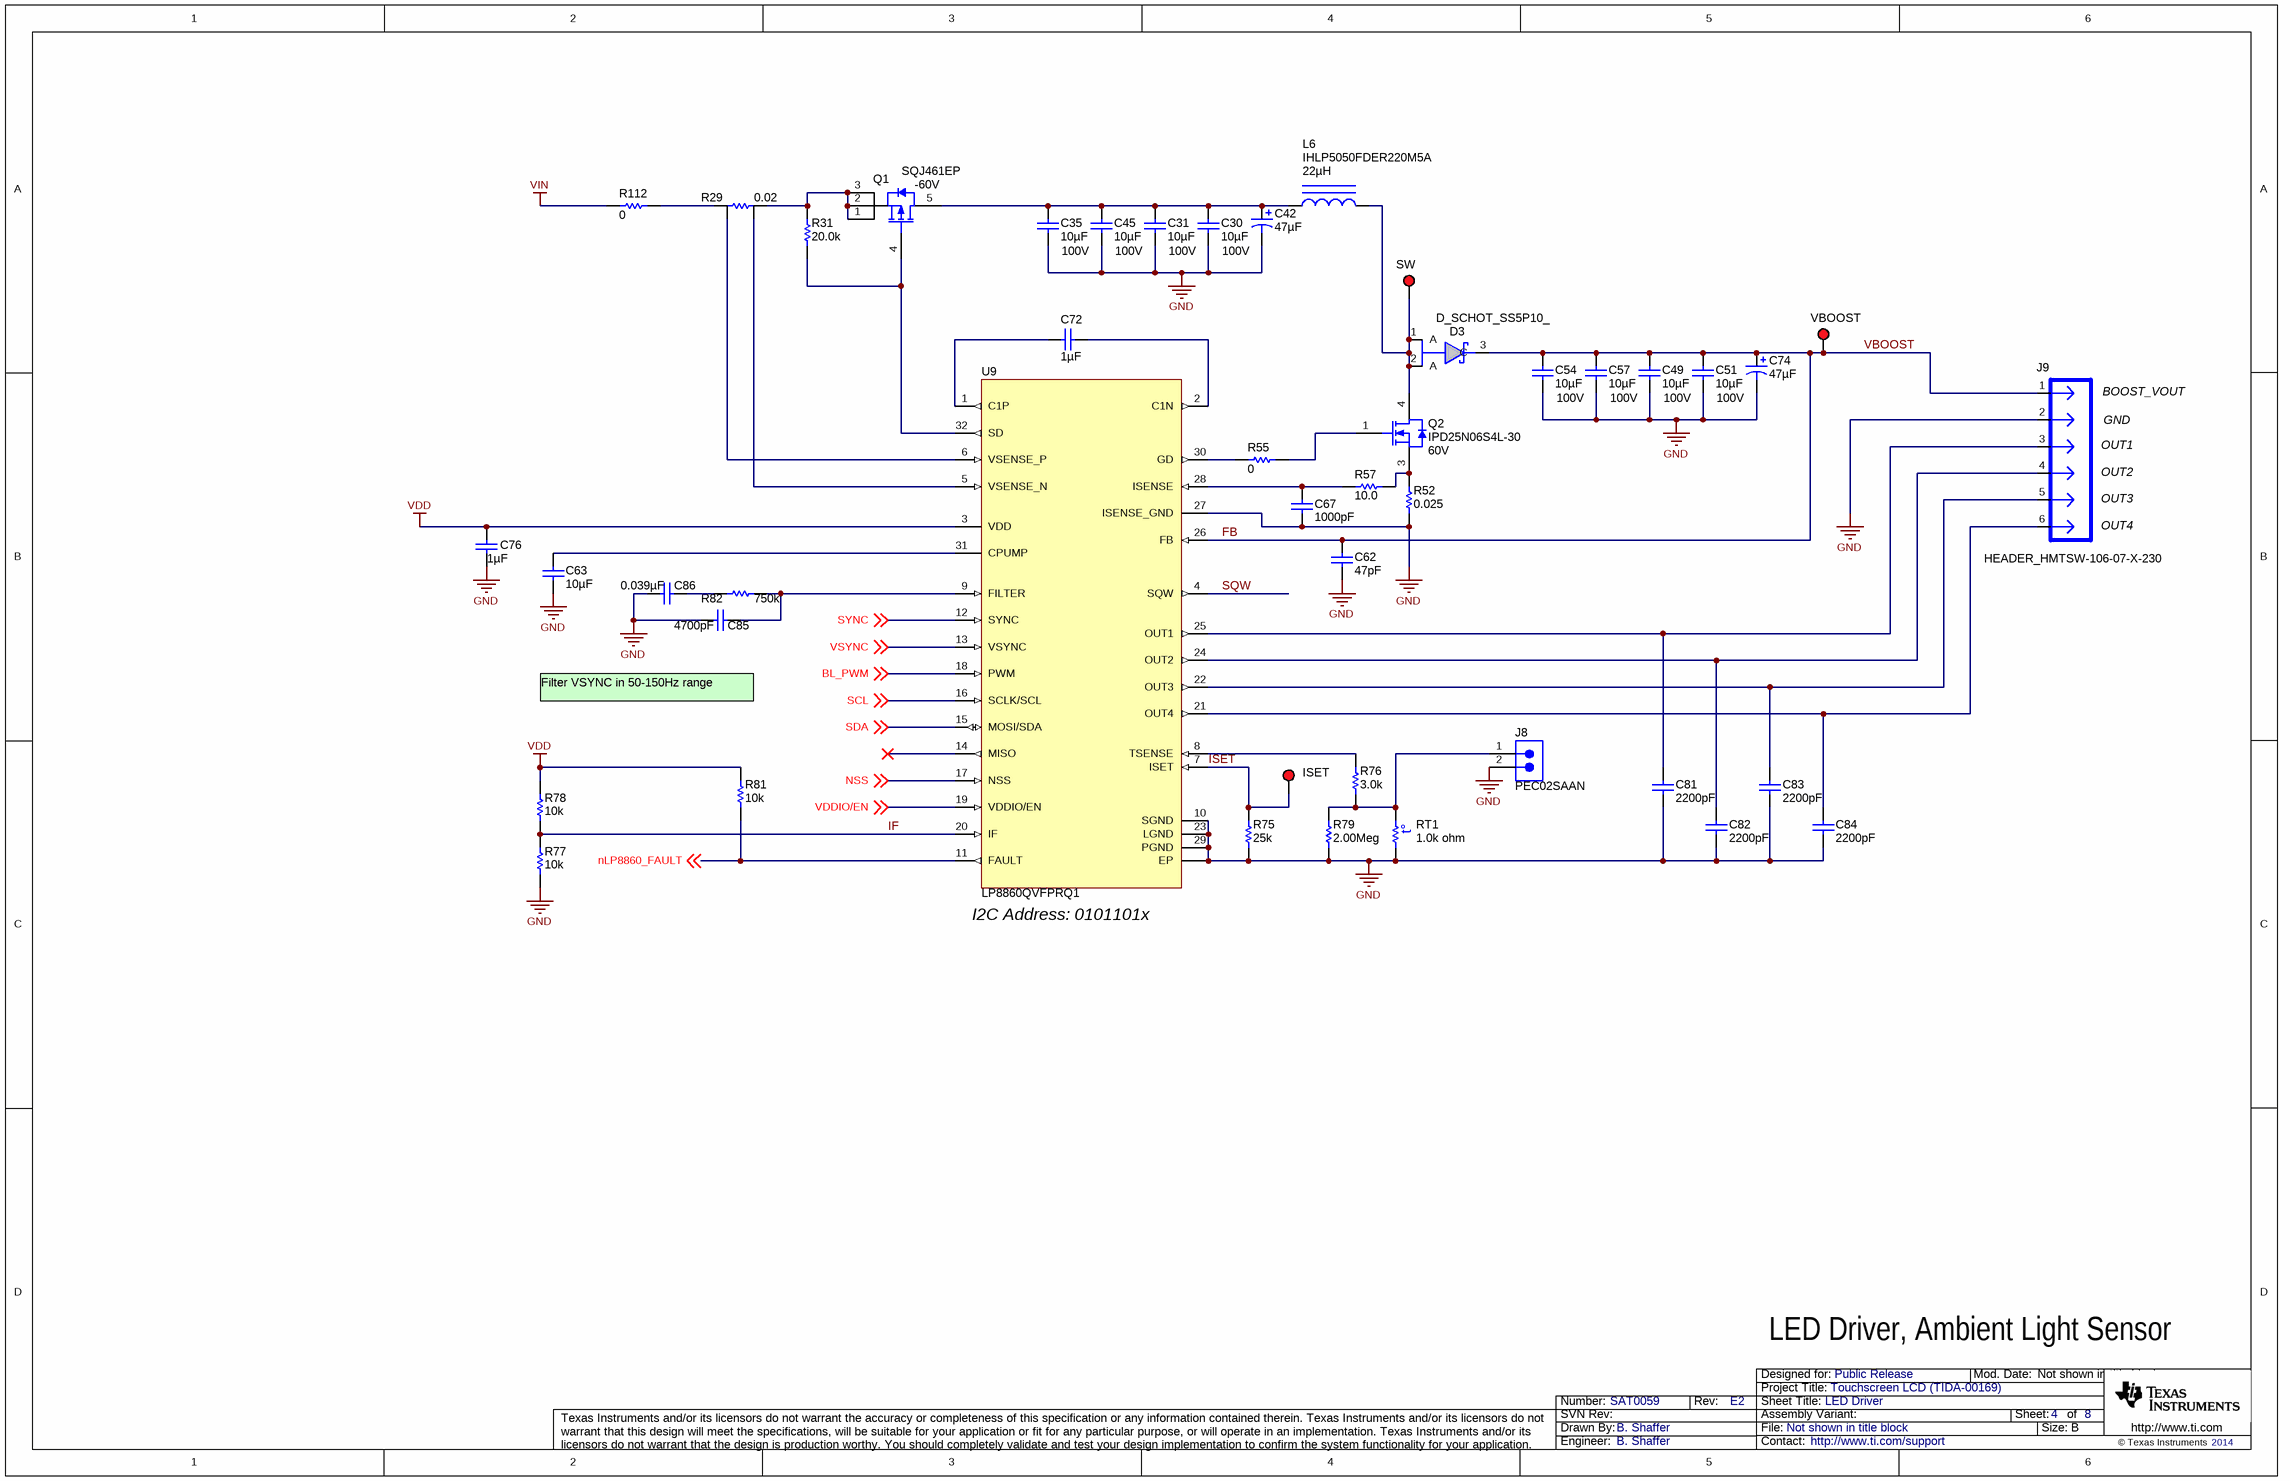
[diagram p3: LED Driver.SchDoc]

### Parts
C30  ValueDisplayed: 10µF  Value2: 100V  [2220]  (hidden comment: C5750X7S2A106M)
C31  ValueDisplayed: 10µF  Value2: 100V  [2220]  (hidden comment: C5750X7S2A106M)
C35  ValueDisplayed: 10µF  Value2: 100V  [2220]  (hidden comment: C5750X7S2A106M)
C42  ValueDisplayed: 47µF  [CAPSMT_62_HA0]  (hidden comment: EMZA630ADA470MHA0G)
C45  ValueDisplayed: 10µF  Value2: 100V  [2220]  (hidden comment: C5750X7S2A106M)
C49  ValueDisplayed: 10µF  Value2: 100V  [2220]  (hidden comment: C5750X7S2A106M)
C51  ValueDisplayed: 10µF  Value2: 100V  [2220]  (hidden comment: C5750X7S2A106M)
C54  ValueDisplayed: 10µF  Value2: 100V  [2220]  (hidden comment: C5750X7S2A106M)
C57  ValueDisplayed: 10µF  Value2: 100V  [2220]  (hidden comment: C5750X7S2A106M)
C62  ValueDisplayed: 47pF  [0603]  (hidden comment: GRM1885C2A470JA01D)
C63  ValueDisplayed: 10µF  [0805_HV]  (hidden comment: GRM21BR61C106KE15L)
C67  ValueDisplayed: 1000pF  [0603]  (hidden comment: GRM188R72A102KA01D)
C72  ValueDisplayed: 1µF  [0603]  (hidden comment: GRM188R71E105KA12D)
C74  ValueDisplayed: 47µF  [CAPSMT_62_HA0]  (hidden comment: EMZA630ADA470MHA0G)
C76  ValueDisplayed: 1µF  [0603]  (hidden comment: GRM188R71E105KA12D)
C81  ValueDisplayed: 2200pF  [0603]  (hidden comment: 06031C222JAT2A)
C82  ValueDisplayed: 2200pF  [0603]  (hidden comment: 06031C222JAT2A)
C83  ValueDisplayed: 2200pF  [0603]  (hidden comment: 06031C222JAT2A)
C84  ValueDisplayed: 2200pF  [0603]  (hidden comment: 06031C222JAT2A)
C85  ValueDisplayed: 4700pF  [0603]  (hidden comment: C1608C0G1E472J)
C86  ValueDisplayed: 0.039µF  [0603]  (hidden comment: GRM188R71C393KA01D)
D3  D_SCHOT_SS5P10_  [TO-277[SMPC]]
ISET  5000  [Keystone5000]  (value not drawn)
J8  PEC02SAAN  [CONN_PEC02SAAN]
J9  HEADER_HMTSW-106-07-X-230  [HDR-100_1X6]
L6  IHLP5050FDER220M5A  ValueDisplayed: 22µH  [IHLP-5050FD]
Q1  SQJ461EP  value -60V  [PowerPAK_SO-8L]
Q2  IPD25N06S4L-30  value 60V  [DPAK]
R29  value 0.02  [2412]  (hidden comment: LVK24R020FER)
R31  value 20.0k  [0603]  (hidden comment: CRCW060320K0FKEA)
R52  value 0.025  [2512M]  (hidden comment: CRA2512-FZ-R025ELF)
R55  value 0  [0603]  (hidden comment: RC0603JR-070RL)
R57  value 10.0  [0603]  (hidden comment: CRCW060310R0FKEA)
R75  value 25k  [0603]  (hidden comment: RC0603FR-0712K4L)
R76  value 3.0k  [0402]  (hidden comment: CRCW04023K00JNED)
R77  value 10k  [0603]  (hidden comment: CRCW060310K0JNEA)
R78  value 10k  [0603]  (hidden comment: CRCW060310K0JNEA)
R79  value 2.00Meg  [0603]  (hidden comment: CRCW06032M00FKEA)
R81  value 10k  [0603]  (hidden comment: CRCW060310K0JNEA)
R82  value 750k  [0603]  (hidden comment: RC0603FR-07750KL)
R112  value 0  [0603]  (hidden comment: RC0603JR-070RL)
RT1  value 1.0k ohm  [0805_HV]  (hidden comment: NCP21XQ102J03RA)
SW  5000  [Keystone5000]  (value not drawn)
U9  LP8860QVFPRQ1  [VFP0032B_N]
VBOOST  5000  [Keystone5000]  (value not drawn)

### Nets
GND: C30.2 C31.2 C35.2 C42.2(-) C45.2 C49.2 C51.2 C54.2 C57.2 C62.2 C63.2 C67.1 C74.2(-) C76.1 C81.2 C82.2 C83.2 C84.2 C85.2 C86.2 J8.2 J9.2 R52.1 R75.1 R77.2 R79.2 RT1.1 U9.10(SGND) U9.23(LGND) U9.27(ISENSE_GND) U9.29(PGND) U9.33(EP)
VDD: C76.2 R78.1 R81.1 U9.3(VDD)
VIN: R112.2
BL_PWM: U9.18(PWM) ; off-sheet BL_PWM
FB: C49.1 C51.1 C54.1 C57.1 C62.1 C74.1(+) D3.3(C) J9.1 U9.26(FB) VBOOST.1  [also labelled VBOOST]
IF: R77.1 R78.2 U9.20(IF)
ISET: ISET.1 R75.2 U9.7(ISET)
nLP8860_FAULT: R81.2 U9.11(FAULT) ; off-sheet nLP8860_FAULT
NSS: U9.17(NSS) ; off-sheet NSS
SCL: U9.16(SCLK/SCL) ; off-sheet SCL
SDA: U9.15(MOSI/SDA) ; off-sheet SDA
SQW: U9.4(SQW)
SYNC: U9.12(SYNC) ; off-sheet SYNC
VDDIO/EN: U9.19(VDDIO/EN) ; off-sheet VDDIO/EN
VSYNC: U9.13(VSYNC) ; off-sheet VSYNC
NetC30_1: C30.1 C31.1 C35.1 C42.1(+) C45.1 L6.1 Q1.5(D)
NetC63_1: C63.1 U9.31(CPUMP)
NetC67_2: C67.2 R57.1 U9.28(ISENSE)
NetC72_1: C72.1 U9.2(C1N)
NetC72_2: C72.2 U9.1(C1P)
NetC81_1: C81.1 J9.3 U9.25(OUT1)
NetC82_1: C82.1 J9.4 U9.24(OUT2)
NetC83_1: C83.1 J9.5 U9.22(OUT3)
NetC84_1: C84.1 J9.6 U9.21(OUT4)
NetC85_1: C85.1 R82.2 U9.9(FILTER)
NetC86_1: C86.1 R82.1
NetD3_1: D3.1(A) D3.2(A) L6.2 Q2.4(D) SW.1
NetJ8_1: J8.1 R76.1 R79.1 RT1.2
NetQ1_1: Q1.1(S) Q1.2(S) Q1.3(S) R29.1 R31.2
NetQ1_4: Q1.4(G) R31.1 U9.32(SD)
NetQ2_1: Q2.1(G) R55.1
NetQ2_3: Q2.3(S) R52.2 R57.2
NetR29_2: R29.2 R112.1
NetR29_3: R29.3 U9.5(VSENSE_N)
NetR29_4: R29.4 U9.6(VSENSE_P)
NetR55_2: R55.2 U9.30(GD)
NetR76_2: R76.2 U9.8(TSENSE)

Not connected (* = marked no-connect by the designer): U9 14(MISO)*

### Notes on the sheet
- GND
- BOOST_VOUT
- OUT1
- OUT2
- OUT3
- OUT4
- Filter VSYNC in 50-150Hz range
- (near U9) I2C Address: 0101101x
- LED Driver, Ambient Light Sensor

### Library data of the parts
C30 C31 C35 C45 C49 C51 C54 C57 = C5750X7S2A106M: CAP, CERM, 10uF, 100V, +/-20%, X7S, 2220; Manufacturer: TDK; Polarized: N; CompType: Capacitor; U/M: EA; Cap_F: 0.00001; Tolerance_%: 20; ESR_Ohm: 0.005; Value1: 0.005 ohm; VDC_V: 100; IRMS_A: 6.45; TaMin_C: -55; TaMax_C: 125
C42 C74 = EMZA630ADA470MHA0G: CAP, AL, 47uF, 63V, +/-20%, 0.7 ohm, SMD; Manufacturer: Nippon Chemi-Con; Polarized: Y; CompType: Capacitor; U/M: EA; Cap_F: 0.000047; Tolerance_%: 20; Value1: 0.7 ohm; VDC_V: 63; ESR_Ohm: 0.7; IRMS_A: 0.25; TaMin_C: -55; TaMax_C: 105; Cap_Case: HA0
C62 = GRM1885C2A470JA01D: CAP, CERM, 47pF, 100V, +/-5%, C0G/NP0, 0603; Manufacturer: MuRata; Polarized: N; CompType: Capacitor; U/M: EA; Cap_F: 0.000000000047; Tolerance_%: 5; Value1: Unknown; VDC_V: 100; TaMin_C: -55; TaMax_C: 125
C63 = GRM21BR61C106KE15L: CAP, CERM, 10uF, 16V, +/-10%, X5R, 0805; Manufacturer: MuRata; Polarized: N; CompType: Capacitor; U/M: EA; Cap_F: 0.00001; Tolerance_%: 10; ESR_Ohm: 0.008; Value1: 0.008 ohm; VDC_V: 16; TaMin_C: -55; TaMax_C: 85; Cap_Case: 0805
C67 = GRM188R72A102KA01D: CAP, CERM, 1000pF, 100V, +/-10%, X7R, 0603; Manufacturer: MuRata; Polarized: N; CompType: Capacitor; U/M: EA; Cap_F: 0.000000001; Tolerance_%: 10; Value1: Unknown; VDC_V: 100; TaMin_C: -55; TaMax_C: 125
C72 C76 = GRM188R71E105KA12D: CAP, CERM, 1uF, 25V, +/-10%, X7R, 0603; Manufacturer: MuRata; Polarized: N; CompType: Capacitor; U/M: EA; Cap_F: 0.000001; Tolerance_%: 10; Value1: Unknown; VDC_V: 25; TaMin_C: -55; TaMax_C: 125
C81-C84 = 06031C222JAT2A: CAP, CERM, 2200pF, 100V, +/-5%, X7R, 0603; Manufacturer: AVX; Polarized: N; CompType: Capacitor; U/M: EA; Cap_F: 0.0000000022; Tolerance_%: 5; ESR_Ohm: 0.192; Value1: 0.192 ohm; VDC_V: 100; TaMin_C: -55; TaMax_C: 125
C85 = C1608C0G1E472J: CAP, CERM, 4700pF, 25V, +/-5%, C0G/NP0, 0603; Manufacturer: TDK; Polarized: N; CompType: Capacitor; U/M: EA; Cap_F: 0.0000000047; Tolerance_%: 5; Value1: Unknown; VDC_V: 25; TaMin_C: -55; TaMax_C: 125
C86 = GRM188R71C393KA01D: CAP, CERM, 0.039uF, 16V, +/-10%, X7R, 0603; Manufacturer: MuRata; Polarized: N; CompType: Capacitor; U/M: EA; Cap_F: 0.000000039; Tolerance_%: 10; Value1: Unknown; VDC_V: 16; TaMin_C: -55; TaMax_C: 125
D3 = D_SCHOT_SS5P10_: Diode, High Current, Schottky Barrier, 5A, 100V; PartNumber: SS5P10-M3xx; Manufacturer: Vishay; AREA: 73600; Value: SS5P10-M3xx
ISET SW VBOOST = 5000: as TP1 on sheet Power Supplies
J8 = PEC02SAAN: Header, 100mil, 2x1, Tin plated, TH; Manufacturer: Sullins Connector Solutions; SymbolCreator: a0412235; U/M: EA
J9 = HEADER_HMTSW-106-07-X-230: Header, 6 pin, 100mil Space, Gold Tail; PartNumber: HMTSW-106-07-x-y-230; Manufacturer: Samtec; Area: 81900; Value: HMTSW-106-07-x-y-230
L6 = IHLP5050FDER220M5A: Inductor, Shielded, Powdered Iron, 22uH, 5.5A, 0.0313 ohm, SMD; Manufacturer: Vishay-Dale; Ind_H: 22.0E-6; Imax_A: 5.5; Irms: 8.3A @ 40C rise; Isat: 5.5A @ 20% inductance drop; DCR_ohm: 0.0313; U/M: EA
Q1 = SQJ461EP: MOSFET, P-CH, -60V, 30A, PowerPAK_SO-8L; Manufacturer: Vishay-Siliconix; Alternate Manufacturer: None; SymbolCreator: a0411947; U/M: EA; ChType: P; VdsMax_V: -60; Value1: 0.031 ohm; Rdson45_Ohm: 0.031; Value2: 90 nC; QgTyp_nC: 90; Vgs_V: 20; IdsMax_A: 30
Q2 = IPD25N06S4L-30: MOSFET, N-CH, 60V, 25A, DPAK; Manufacturer: Infineon Technologies; Alternate Manufacturer: None; U/M: EA; ChType: N; VdsMax_V: 60; Value1: 0.03 ohm; Rdson45_Ohm: 0.03; Value2: 3.9 nC; QgTyp_nC: 3.9; Vgs_V: 16; IdsMax_A: 25
R29 = LVK24R020FER: RES, 0.02 ohm, 1%, 1W, 2412; Manufacturer: Ohmite; CompType: Resistor; Value_Code: R020; Tolerance_%: 1; TempCo: 50 ppm/C; EIA_Code: E96; U/M: EA
R31 = CRCW060320K0FKEA: RES, 20.0k ohm, 1%, 0.1W, 0603; Manufacturer: Vishay-Dale; CompType: Resistor; Res_ohm: 20000; Value_Code: 20k0; Tolerance_%: 1; Power_W: 0.1; VDC_V: 75; TempCo: 100 ppm/C; EIA_Code: E96; U/M: EA
R52 = CRA2512-FZ-R025ELF: RES, 0.025 ohm, 1%, 3W, 2512; Manufacturer: Bourns; CompType: Resistor; Value_Code: R025; Tolerance_%: 1; Power_W: 3; VDC_V: 0; TempCo: 75 ppm/C; EIA_Code: E96; U/M: EA
R55 R112 = RC0603JR-070RL: RES, 0 ohm, 5%, 0.1W, 0603; Manufacturer: Yageo America; CompType: Resistor; Value_Code: 0000; Tolerance_%: 5; Power_W: 0.1; VDC_V: 50; TempCo: 200 ppm/C; EIA_Code: E24; U/M: EA
R57 = CRCW060310R0FKEA: RES, 10.0 ohm, 1%, 0.1W, 0603; Manufacturer: Vishay-Dale; CompType: Resistor; Res_ohm: 10; Value_Code: 10R0; Tolerance_%: 1; Power_W: 0.1; VDC_V: 75; TempCo: 100 ppm/C; EIA_Code: E96; U/M: EA
R75 = RC0603FR-0712K4L: RES, 12.4k ohm, 1%, 0.1W, 0603; Manufacturer: Yageo America; CompType: Resistor; Res_ohm: 12400; Value_Code: 12k4; Tolerance_%: 1; Power_W: 0.1; VDC_V: 150; TempCo: 200 ppm/C; EIA_Code: E96; U/M: EA
R76 = CRCW04023K00JNED: RES, 3.0k ohm, 5%, 0.063W, 0402; Manufacturer: Vishay-Dale; CompType: Resistor; Res_ohm: 3000; Value_Code: 3k00; Tolerance_%: 5; Power_W: 0.063; VDC_V: 50; TempCo: 200 ppm/C; EIA_Code: E24; U/M: EA
R77 R78 R81 = CRCW060310K0JNEA: as R5 on sheet Power Supplies
R79 = CRCW06032M00FKEA: RES, 2.00Meg ohm, 1%, 0.1W, 0603; Manufacturer: Vishay-Dale; CompType: Resistor; Res_ohm: 2000000; Value_Code: 2M00; Tolerance_%: 1; Power_W: 0.1; VDC_V: 75; TempCo: 100 ppm/C; EIA_Code: E96; U/M: EA
R82 = RC0603FR-07750KL: RES, 750k ohm, 1%, 0.1W, 0603; Manufacturer: Yageo America; CompType: Resistor; Res_ohm: 750000; Tolerance_%: 1; Power_W: 0.1; VDC_V: 150; TempCo: 200 ppm/C; EIA_Code: E96; U/M: EA
RT1 = NCP21XQ102J03RA: Thermistor NTC, 1.0k ohm, 5%, 0805; Manufacturer: MuRata; Tolerance_%: 5; Power_W: 0.2; TaMin_C: -40; TaMax_C: 125; U/M: EA
U9 = LP8860QVFPRQ1: LOW EMI, High Performance 4-Channel LED Driver for Automotive Lighting, VFP0032B; Alternate Manufacturer: None; Manufacturer: Texas Instruments; SymbolCreator: a0799628; CompType: IC; U/M: EA

## Sheet Haptic Drivers.SchDoc: Haptic Drivers
size 431 x 279 mm; Date: Not shown in title block; ApprovedBy: Not shown in title block; CheckedBy: Not shown in title block; Author: Not shown in title block; CompanyName: Not shown in title block; DrawnBy: B. Shaffer; Engineer: Not shown in title block; Organization: Not shown in title block; Address1: Not shown in title block; Address2: Not shown in title block; Address3: Not shown in title block; Address4: Not shown in title block; DocumentNumber: 5; Revision: Use project parameter SCH_Rev; SheetNumber: 5; SheetTotal: 8; PageSetup: Record=PageOptions|CenterHorizontal=True|CenterVertical=True|PrintScale=0.96|XCorrection=1.00|YCorrection=1.00|PrintKind=0|BorderSize=5000000|LeftOffset=0|BottomOffset=0|Orientation=2|PaperLength=1000|PaperWidth=1000|Scale=100|PaperSource=15|PrintQuality=600|MediaType=1|DitherType=10|PaperKind=11x17|PrintScaleMode=1
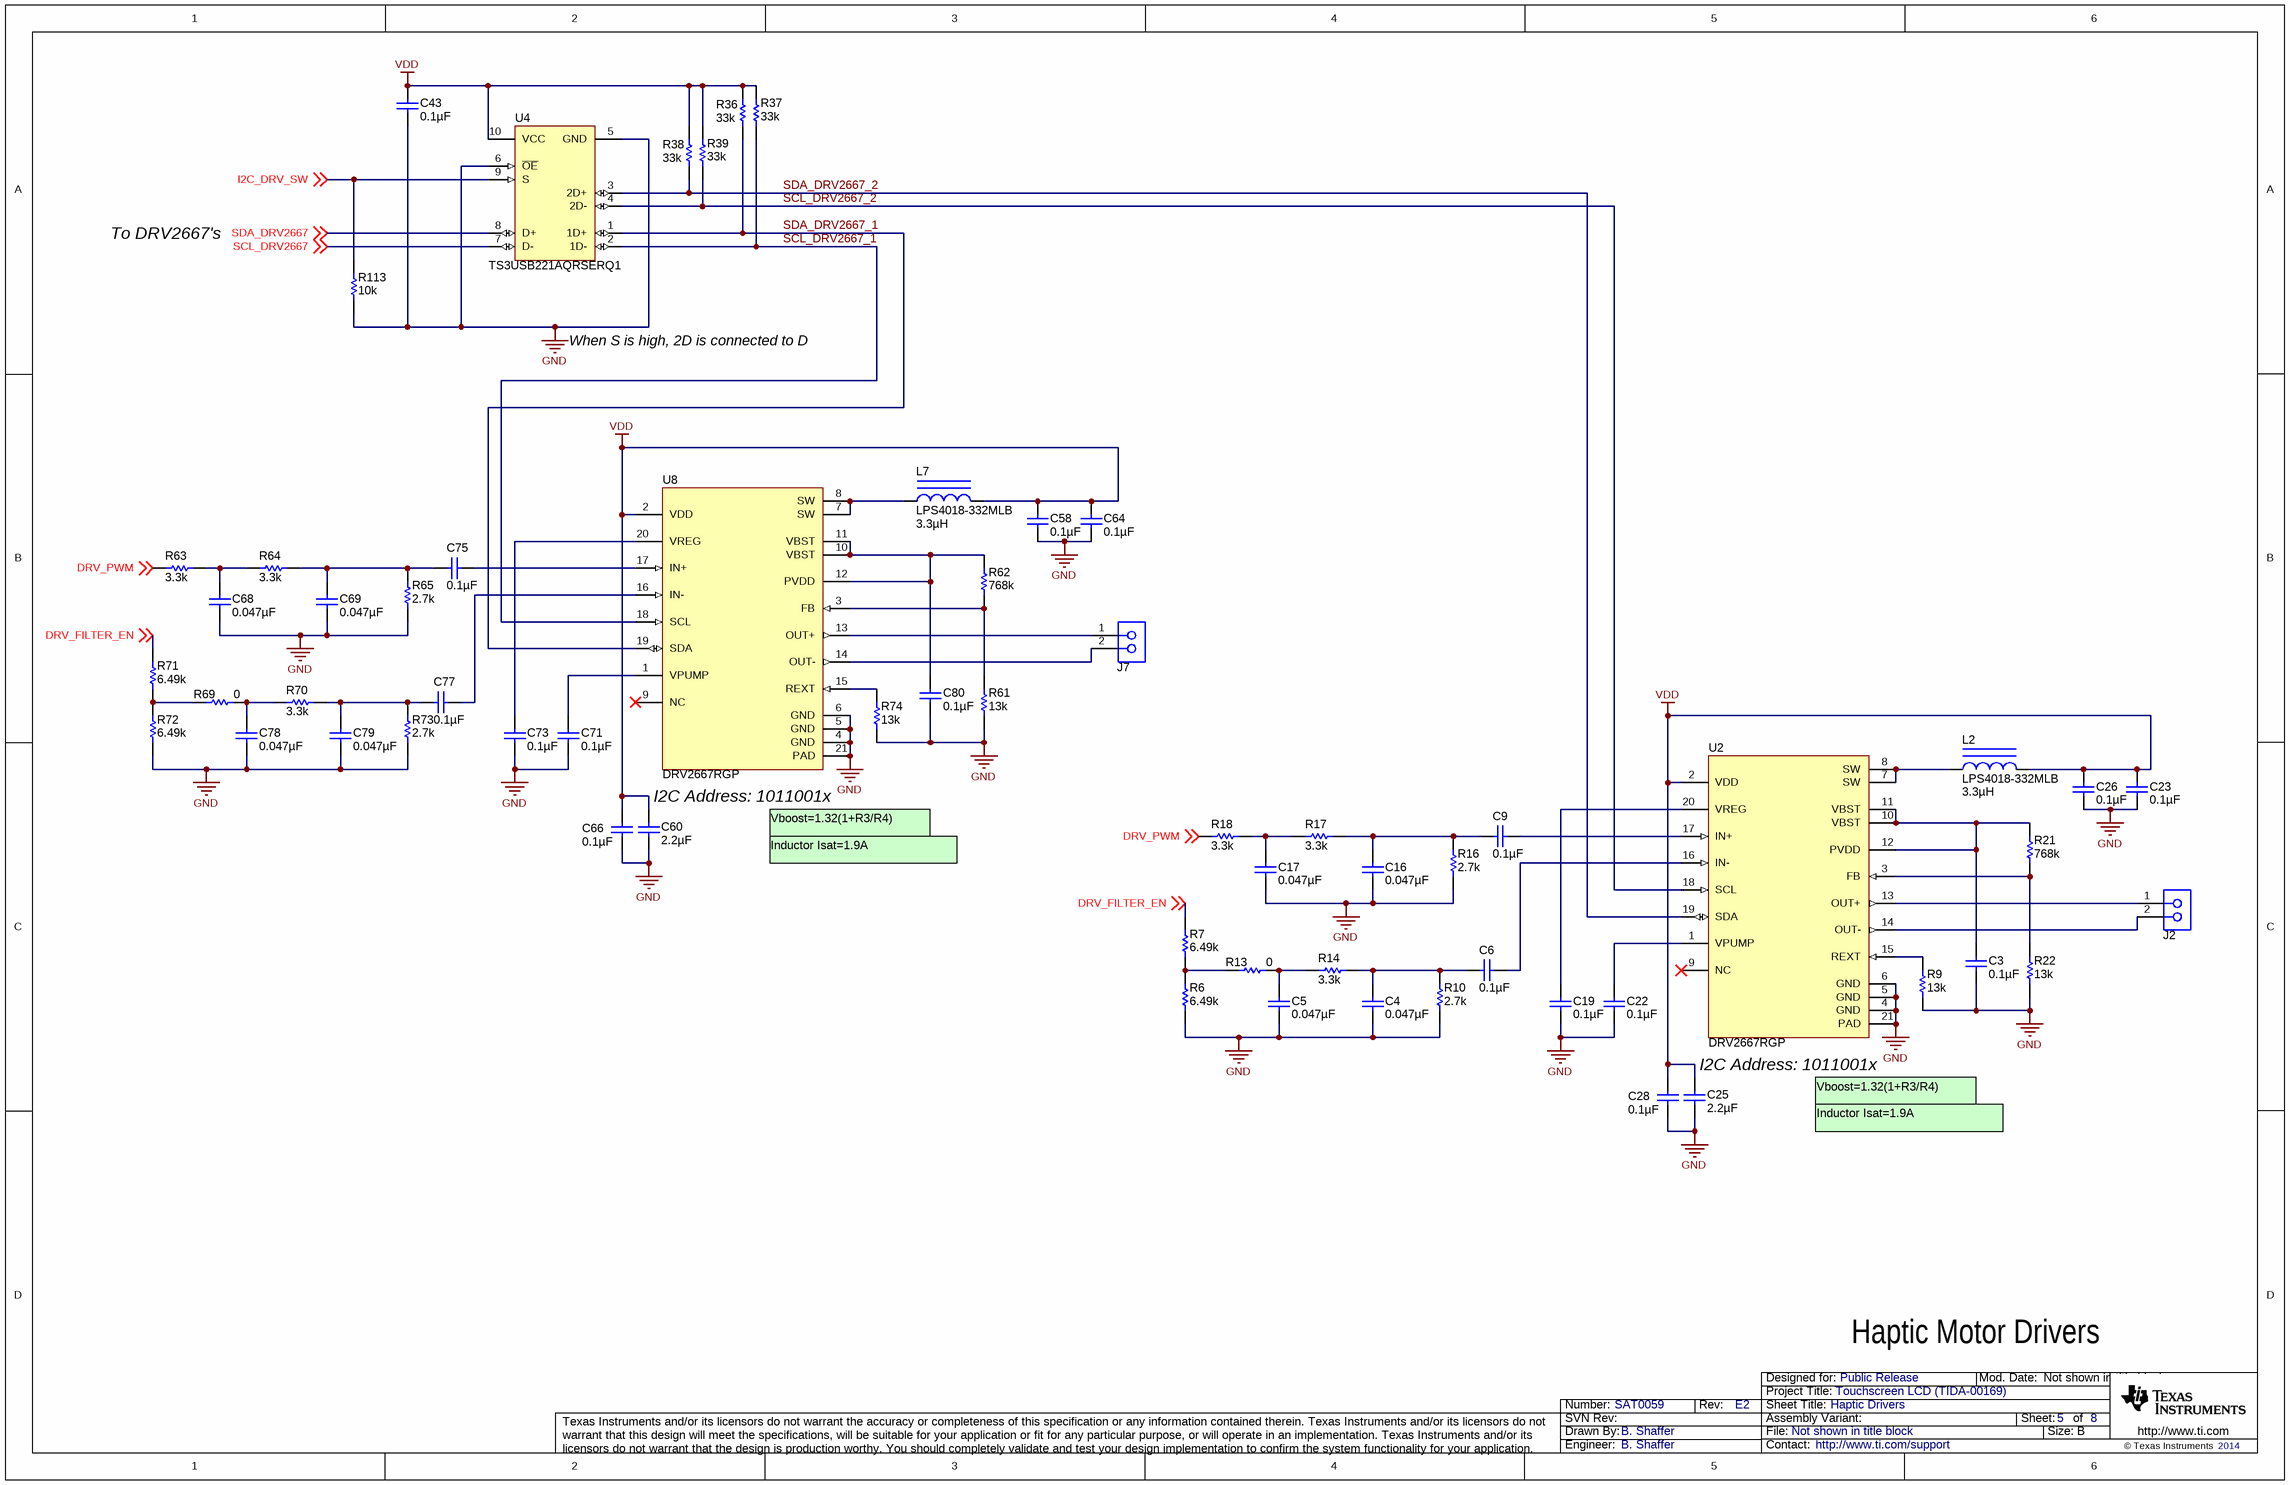
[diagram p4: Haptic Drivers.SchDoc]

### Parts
C3  ValueDisplayed: 0.1µF  [1206]  (hidden comment: GRM31CR72E104KW03L)
C4  ValueDisplayed: 0.047µF  [0402]  (hidden comment: C1005X7R1C473K)
C5  ValueDisplayed: 0.047µF  [0402]  (hidden comment: C1005X7R1C473K)
C6  ValueDisplayed: 0.1µF  [0603]  (hidden comment: 0603YC104JAT2A)
C9  ValueDisplayed: 0.1µF  [0603]  (hidden comment: 0603YC104JAT2A)
C16  ValueDisplayed: 0.047µF  [0402]  (hidden comment: C1005X7R1C473K)
C17  ValueDisplayed: 0.047µF  [0402]  (hidden comment: C1005X7R1C473K)
C19  ValueDisplayed: 0.1µF  [0402]  (hidden comment: GRM155R61C104KA88D)
C22  ValueDisplayed: 0.1µF  [0402]  (hidden comment: GRM155R61C104KA88D)
C23  ValueDisplayed: 0.1µF  [1206]  (hidden comment: 12061C104KAT2A)
C25  ValueDisplayed: 2.2µF  [0805_HV]  (hidden comment: C0805C225K4RACTU)
C26  ValueDisplayed: 0.1µF  [1206]  (hidden comment: 12061C104KAT2A)
C28  ValueDisplayed: 0.1µF  [1206]  (hidden comment: 12061C104KAT2A)
C43  ValueDisplayed: 0.1µF  [0603]  (hidden comment: 0603YC104JAT2A)
C58  ValueDisplayed: 0.1µF  [1206]  (hidden comment: 12061C104KAT2A)
C60  ValueDisplayed: 2.2µF  [0805_HV]  (hidden comment: C0805C225K4RACTU)
C64  ValueDisplayed: 0.1µF  [1206]  (hidden comment: 12061C104KAT2A)
C66  ValueDisplayed: 0.1µF  [1206]  (hidden comment: 12061C104KAT2A)
C68  ValueDisplayed: 0.047µF  [0402]  (hidden comment: C1005X7R1C473K)
C69  ValueDisplayed: 0.047µF  [0402]  (hidden comment: C1005X7R1C473K)
C71  ValueDisplayed: 0.1µF  [0402]  (hidden comment: GRM155R61C104KA88D)
C73  ValueDisplayed: 0.1µF  [0402]  (hidden comment: GRM155R61C104KA88D)
C75  ValueDisplayed: 0.1µF  [0603]  (hidden comment: 0603YC104JAT2A)
C77  ValueDisplayed: 0.1µF  [0603]  (hidden comment: 0603YC104JAT2A)
C78  ValueDisplayed: 0.047µF  [0402]  (hidden comment: C1005X7R1C473K)
C79  ValueDisplayed: 0.047µF  [0402]  (hidden comment: C1005X7R1C473K)
C80  ValueDisplayed: 0.1µF  [1206]  (hidden comment: GRM31CR72E104KW03L)
J2  1727010  [PhoenixConact_1727010]  (value not drawn)
J7  1727010  [PhoenixConact_1727010]  (value not drawn)
L2  LPS4018-332MLB  ValueDisplayed: 3.3µH  [LPS4018]
L7  LPS4018-332MLB  ValueDisplayed: 3.3µH  [LPS4018]
R6  value 6.49k  [0402]  (hidden comment: CRCW04026K49FKED)
R7  value 6.49k  [0402]  (hidden comment: CRCW04026K49FKED)
R9  value 13k  [0603]  (hidden comment: CRCW060313K0JNEA)
R10  value 2.7k  [0402]  (hidden comment: CRCW04022K70JNED)
R13  value 0  [0603]  (hidden comment: CRCW06030000Z0EA)
R14  value 3.3k  [0402]  (hidden comment: CRCW04023K30JNED)
R16  value 2.7k  [0402]  (hidden comment: CRCW04022K70JNED)
R17  value 3.3k  [0402]  (hidden comment: CRCW04023K30JNED)
R18  value 3.3k  [0402]  (hidden comment: CRCW04023K30JNED)
R21  value 768k  [0402]  (hidden comment: CRCW0402768KFKED)
R22  value 13k  [0603]  (hidden comment: CRCW060313K0JNEA)
R36  value 33k  [0402]  (hidden comment: CRCW040233K0JNED)
R37  value 33k  [0402]  (hidden comment: CRCW040233K0JNED)
R38  value 33k  [0402]  (hidden comment: CRCW040233K0JNED)
R39  value 33k  [0402]  (hidden comment: CRCW040233K0JNED)
R61  value 13k  [0603]  (hidden comment: CRCW060313K0JNEA)
R62  value 768k  [0402]  (hidden comment: CRCW0402768KFKED)
R63  value 3.3k  [0402]  (hidden comment: CRCW04023K30JNED)
R64  value 3.3k  [0402]  (hidden comment: CRCW04023K30JNED)
R65  value 2.7k  [0402]  (hidden comment: CRCW04022K70JNED)
R69  value 0  [0603]  (hidden comment: CRCW06030000Z0EA)
R70  value 3.3k  [0402]  (hidden comment: CRCW04023K30JNED)
R71  value 6.49k  [0402]  (hidden comment: CRCW04026K49FKED)
R72  value 6.49k  [0402]  (hidden comment: CRCW04026K49FKED)
R73  value 2.7k  [0402]  (hidden comment: CRCW04022K70JNED)
R74  value 13k  [0603]  (hidden comment: CRCW060313K0JNEA)
R113  value 10k  [0603]  (hidden comment: CRCW060310K0JNEA)
U2  DRV2667RGP  [RGP0020D]
U4  TS3USB221AQRSERQ1  [RSE0010A]
U8  DRV2667RGP  [RGP0020D]

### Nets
GND: C3.2 C4.2 C5.2 C16.2 C17.2 C19.2 C22.2 C23.2 C25.2 C26.2 C28.2 C43.2 C58.2 C60.2 C64.2 C66.2 C68.2 C69.2 C71.2 C73.2 C78.2 C79.2 C80.2 R6.1 R9.1 R10.1 R16.1 R22.1 R61.1 R65.1 R72.1 R73.1 R74.1 R113.2 U2.4(GND) U2.5(GND) U2.6(GND) U2.21(PAD) U4.5(GND) U4.6(~{OE}) U8.4(GND) U8.5(GND) U8.6(GND) U8.21(PAD)
VDD: C23.1 C25.1 C26.1 C28.1 C43.1 C58.1 C60.1 C64.1 C66.1 L2.2 L7.2 R36.2 R37.2 R38.2 R39.2 U2.2(VDD) U4.10(VCC) U8.2(VDD)
DRV_FILTER_EN: R7.2 R71.2 ; off-sheet DRV_FILTER_EN
DRV_PWM: R18.1 R63.1 ; off-sheet DRV_PWM
I2C_DRV_SW: R113.1 U4.9(S) ; off-sheet I2C_DRV_SW
SCL_DRV2667: U4.7(D-) ; off-sheet SCL_DRV2667
SCL_DRV2667_1: R37.1 U4.2(1D-) U8.18(SCL)
SCL_DRV2667_2: R39.1 U2.18(SCL) U4.4(2D-)
SDA_DRV2667: U4.8(D+) ; off-sheet SDA_DRV2667
SDA_DRV2667_1: R36.1 U4.1(1D+) U8.19(SDA)
SDA_DRV2667_2: R38.1 U2.19(SDA) U4.3(2D+)
NetC3_1: C3.1 R21.2 U2.10(VBST) U2.11(VBST) U2.12(PVDD)
NetC4_1: C4.1 C6.2 R10.2 R14.2
NetC5_1: C5.1 R13.1 R14.1
NetC6_1: C6.1 U2.16(IN-)
NetC9_1: C9.1 U2.17(IN+)
NetC9_2: C9.2 C16.1 R16.2 R17.2
NetC17_1: C17.1 R17.1 R18.2
NetC19_1: C19.1 U2.20(VREG)
NetC22_1: C22.1 U2.1(VPUMP)
NetC68_1: C68.1 R63.2 R64.1
NetC69_1: C69.1 C75.2 R64.2 R65.2
NetC71_1: C71.1 U8.1(VPUMP)
NetC73_1: C73.1 U8.20(VREG)
NetC75_1: C75.1 U8.17(IN+)
NetC77_1: C77.1 U8.16(IN-)
NetC77_2: C77.2 C79.1 R70.2 R73.2
NetC78_1: C78.1 R69.1 R70.1
NetC80_1: C80.1 R62.2 U8.10(VBST) U8.11(VBST) U8.12(PVDD)
NetJ2_1: J2.1 U2.13(OUT+)
NetJ2_2: J2.2 U2.14(OUT-)
NetJ7_1: J7.1 U8.13(OUT+)
NetJ7_2: J7.2 U8.14(OUT-)
NetL2_1: L2.1 U2.7(SW) U2.8(SW)
NetL7_1: L7.1 U8.7(SW) U8.8(SW)
NetR6_2: R6.2 R7.1 R13.2
NetR9_2: R9.2 U2.15(REXT)
NetR21_1: R21.1 R22.2 U2.3(FB)
NetR61_2: R61.2 R62.1 U8.3(FB)
NetR69_2: R69.2 R71.1 R72.2
NetR74_2: R74.2 U8.15(REXT)

Not connected (* = marked no-connect by the designer): U2 9(NC)*; U8 9(NC)*

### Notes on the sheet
- To DRV2667's
- When S is high, 2D is connected to D
- I2C Address: 1011001x
- Vboost=1.32(1+R3/R4)
- Inductor Isat=1.9A
- Haptic Motor Drivers

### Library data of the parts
C3 C80 = GRM31CR72E104KW03L: CAP, CERM, 0.1uF, 250V, +/-10%, X7R, 1206; Manufacturer: MuRata; Polarized: N; CompType: Capacitor; U/M: EA; Cap_F: 0.0000001; Tolerance_%: 10; Value1: Unknown; VDC_V: 250; TaMin_C: -55; TaMax_C: 125
C4 C5 C16 C17 C68 C69 C78 C79 = C1005X7R1C473K: CAP, CERM, 0.047uF, 16V, +/-10%, X7R, 0402; Manufacturer: TDK; Polarized: N; CompType: Capacitor; U/M: EA; Cap_F: 0.000000047; Tolerance_%: 10; ESR_Ohm: 0.0305; Value1: 0.0305 ohm; VDC_V: 16; TaMin_C: -55; TaMax_C: 125
C6 C9 C43 C75 C77 = 0603YC104JAT2A: as C27 on sheet Deserializer
C19 C22 C71 C73 = GRM155R61C104KA88D: CAP, CERM, 0.1uF, 16V, +/-10%, X5R, 0402; Manufacturer: MuRata; Polarized: N; CompType: Capacitor; U/M: EA; Cap_F: 0.0000001; Tolerance_%: 10; Value1: Unknown; VDC_V: 16; TaMin_C: -55; TaMax_C: 85
C23 C26 C28 C58 C64 C66 = 12061C104KAT2A: CAP, CERM, 0.1uF, 100V, +/-10%, X7R, 1206; Manufacturer: AVX; Polarized: N; CompType: Capacitor; U/M: EA; Cap_F: 0.0000001; Tolerance_%: 10; ESR_Ohm: 0.037; Value1: 0.037 ohm; VDC_V: 100; TaMin_C: -55; TaMax_C: 125
C25 C60 = C0805C225K4RACTU: CAP, CERM, 2.2uF, 16V, +/-10%, X7R, 0805; Manufacturer: Kemet; Polarized: N; CompType: Capacitor; U/M: EA; Cap_F: 0.0000022; Tolerance_%: 10; ESR_Ohm: 0.008; Value1: 0.008 ohm; VDC_V: 16; IRMS_A: 15.55; TaMin_C: -55; TaMax_C: 125; Cap_Case: 0805
J2 J7 = 1727010: as J3 on sheet Power Supplies
L2 L7 = LPS4018-332MLB: Inductor, Shielded Drum Core, Ferrite, 3.3uH, 1.9A, 0.08 ohm, SMD; Manufacturer: Coilcraft; Ind_H: 3.3E-6; Imax_A: 1.9; Irms: 1.9A @ 40C rise; Isat: 2A @ 30% inductance drop; DCR_ohm: 0.08; U/M: EA
R6 R7 R71 R72 = CRCW04026K49FKED: RES, 6.49k ohm, 1%, 0.063W, 0402; Manufacturer: Vishay-Dale; CompType: Resistor; Res_ohm: 6490; Value_Code: 6k49; Tolerance_%: 1; Power_W: 0.063; VDC_V: 50; TempCo: 100 ppm/C; EIA_Code: E96; U/M: EA
R9 R22 R61 R74 = CRCW060313K0JNEA: RES, 13k ohm, 5%, 0.1W, 0603; Manufacturer: Vishay-Dale; CompType: Resistor; Res_ohm: 13000; Value_Code: 13k0; Tolerance_%: 5; Power_W: 0.1; VDC_V: 75; TempCo: 200 ppm/C; EIA_Code: E24; U/M: EA
R10 R16 R65 R73 = CRCW04022K70JNED: RES, 2.7k ohm, 5%, 0.063W, 0402; Manufacturer: Vishay-Dale; CompType: Resistor; Res_ohm: 2700; Value_Code: 2k70; Tolerance_%: 5; Power_W: 0.063; VDC_V: 50; TempCo: 200 ppm/C; EIA_Code: E24; U/M: EA
R13 R69 = CRCW06030000Z0EA: as R15 on sheet Power Supplies
R14 R17 R18 R63 R64 R70 = CRCW04023K30JNED: RES, 3.3k ohm, 5%, 0.063W, 0402; Manufacturer: Vishay-Dale; CompType: Resistor; Res_ohm: 3300; Value_Code: 3k30; Tolerance_%: 5; Power_W: 0.063; VDC_V: 50; TempCo: 200 ppm/C; EIA_Code: E24; U/M: EA
R21 R62 = CRCW0402768KFKED: RES, 768k ohm, 1%, 0.063W, 0402; Manufacturer: Vishay-Dale; CompType: Resistor; Res_ohm: 768000; Tolerance_%: 1; Power_W: 0.063; VDC_V: 50; TempCo: 100 ppm/C; EIA_Code: E96; U/M: EA
R36-R39 = CRCW040233K0JNED: RES, 33k ohm, 5%, 0.063W, 0402; Manufacturer: Vishay-Dale; CompType: Resistor; Res_ohm: 33000; Value_Code: 33k0; Tolerance_%: 5; Power_W: 0.063; VDC_V: 50; TempCo: 200 ppm/C; EIA_Code: E24; U/M: EA
R113 = CRCW060310K0JNEA: as R5 on sheet Power Supplies
U2 U8 = DRV2667RGP: Piezo Haptic Driver with Boost, Digital Front End, and Internal Waveform Memory, RGP0020D; Alternate Manufacturer: None; Manufacturer: Texas Instruments; SymbolCreator: a0412235; CompType: IC; U/M: EA
U4 = TS3USB221AQRSERQ1: Automotive Catalog ESD Protected, High-Speed USB 2.0 (480-Mbps) 1:2 Multiplexer / Demultiplexer Switch, 16 ohm RON, 2.5 to 3.3V, -40 to 125 degC, 10-Pin UQFN (RSE), Green (RoHS & no Sb/Br); Manufacturer: Texas Instruments; Alternate Manufacturer: None; Alternate PartNumber: Equivalent; SubFamily: USB Switch; Number of Channels: 2; Architecture: 1; ESD HBM(kV): +/-7; ICC(uA): 30; tpd max(ns): 0.25; ron(max)(ohms): 16; RON Mis-match(Max)(Ohms): 0.2; Bandwidth(MHz): 900; ON Time(Max)(ns): 12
